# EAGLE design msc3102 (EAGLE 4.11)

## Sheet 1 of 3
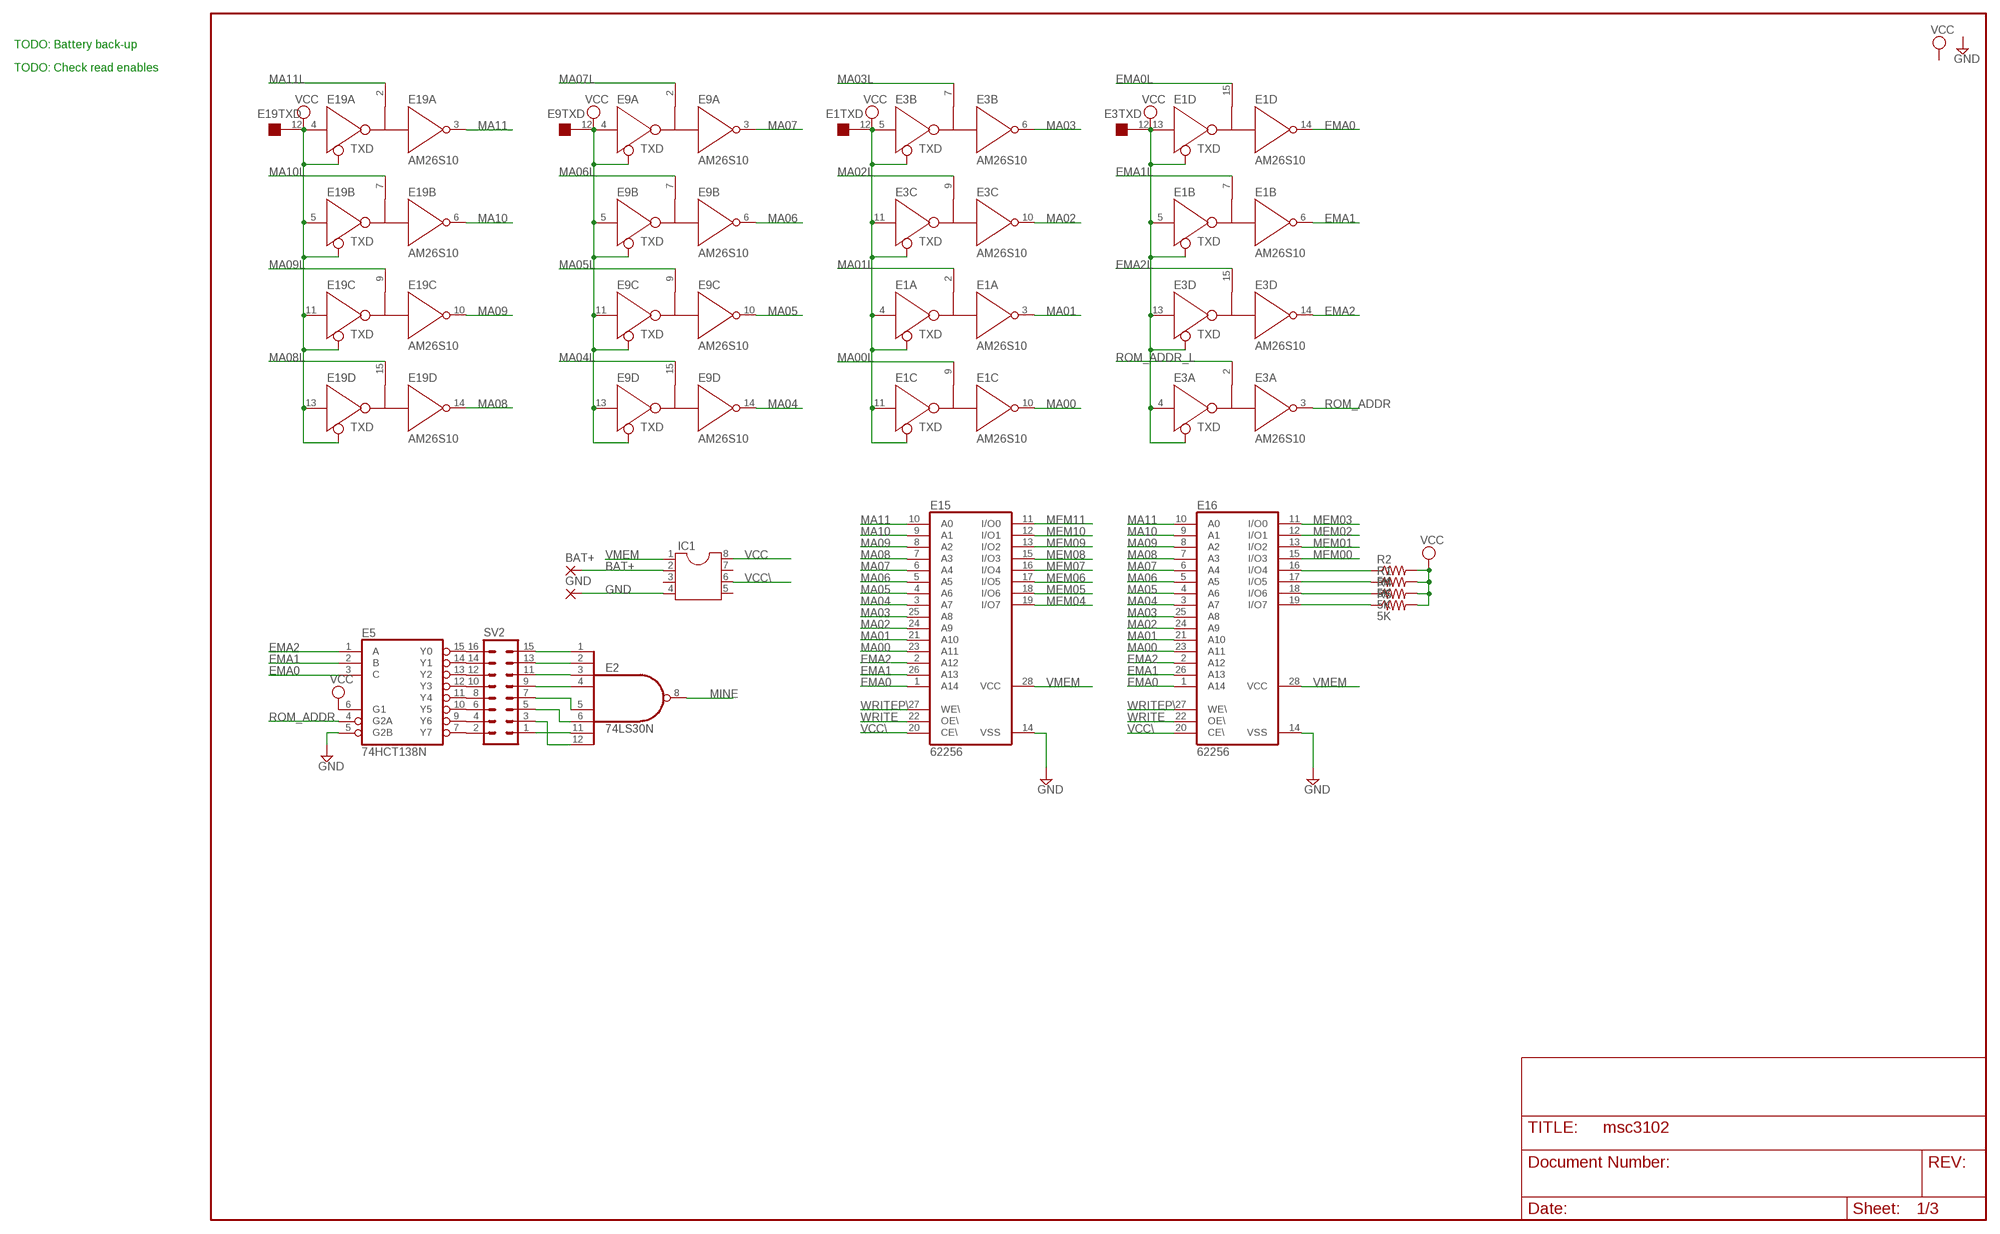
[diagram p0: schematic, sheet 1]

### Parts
BAT+  2,15/1,0  [2,15/1,0]
E1  AM26S10  [DIL16]
E2  74LS30N  [DIL14]
E3  AM26S10  [DIL16]
E5  74HCT138N  [DIL16]
E9  AM26S10  [DIL16]
E15  62256  58C256P  [DIL28-6]
E16  62256  58C256P  [DIL28-6]
E19  AM26S10  [DIL16]
GND  2,15/1,0  [2,15/1,0]
IC1  DIL8  [DIL08]
R1  5K  R-US_0207/10  [0207/10]
R2  5K  R-US_0207/10  [0207/10]
R4  5K  R-US_0207/10  [0207/10]
R5  5K  R-US_0207/10  [0207/10]
SV2  MA08-2  [MA08-2]

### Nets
BAT+: BAT+.1(P) IC1.2
EMA0: E1.14(D:R) E5.3(C) E15.1(A14) E16.1(A14)
EMA0L: E1.15(D:B) ; also sheet 3
EMA1: E1.6(B:R) E5.2(B) E15.26(A13) E16.26(A13)
EMA1L: E1.7(B:B) ; also sheet 3
EMA2: E3.14(D:R) E5.1(A) E15.2(A12) E16.2(A12)
EMA2L: E3.15(D:B) ; also sheet 3
GND [supply]: E5.5(G2B) E15.14(VSS) E16.14(VSS) GND.1(P) IC1.4 ; also sheet 2,3
MA00: E1.10(C:R) E15.23(A11) E16.23(A11)
MA00L: E1.9(C:B) ; also sheet 3
MA01: E1.3(A:R) E15.21(A10) E16.21(A10)
MA01L: E1.2(A:B) ; also sheet 3
MA02: E3.10(C:R) E15.24(A9) E16.24(A9)
MA02L: E3.9(C:B) ; also sheet 3
MA03: E3.6(B:R) E15.25(A8) E16.25(A8)
MA03L: E3.7(B:B) ; also sheet 3
MA04: E9.14(D:R) E15.3(A7) E16.3(A7)
MA04L: E9.15(D:B) ; also sheet 3
MA05: E9.10(C:R) E15.4(A6) E16.4(A6)
MA05L: E9.9(C:B) ; also sheet 3
MA06: E9.6(B:R) E15.5(A5) E16.5(A5)
MA06L: E9.7(B:B) ; also sheet 3
MA07: E9.3(A:R) E15.6(A4) E16.6(A4)
MA07L: E9.2(A:B) ; also sheet 3
MA08: E15.7(A3) E16.7(A3) E19.14(D:R)
MA08L: E19.15(D:B) ; also sheet 3
MA09: E15.8(A2) E16.8(A2) E19.10(C:R)
MA09L: E19.9(C:B) ; also sheet 3
MA10: E15.9(A1) E16.9(A1) E19.6(B:R)
MA10L: E19.7(B:B) ; also sheet 3
MA11: E15.10(A0) E16.10(A0) E19.3(A:R)
MA11L: E19.2(A:B) ; also sheet 3
MEM00: E16.15(I/O3) ; also sheet 2
MEM01: E16.13(I/O2) ; also sheet 2
MEM02: E16.12(I/O1) ; also sheet 2
MEM03: E16.11(I/O0) ; also sheet 2
MEM04: E15.19(I/O7) ; also sheet 2
MEM05: E15.18(I/O6) ; also sheet 2
MEM06: E15.17(I/O5) ; also sheet 2
MEM07: E15.16(I/O4) ; also sheet 2
MEM08: E15.15(I/O3) ; also sheet 2
MEM09: E15.13(I/O2) ; also sheet 2
MEM10: E15.12(I/O1) ; also sheet 2
MEM11: E15.11(I/O0) ; also sheet 2
MINE: E2.8(O) ; also sheet 2
N$1: E5.7(Y7) SV2.2
N$18: E5.9(Y6) SV2.4
N$19: E5.10(Y5) SV2.6
N$20: E5.11(Y4) SV2.8
N$21: E5.12(Y3) SV2.10
N$22: E5.13(Y2) SV2.12
N$23: E5.14(Y1) SV2.14
N$24: E5.15(Y0) SV2.16
N$26: E2.4(I3) SV2.9
N$27: E2.3(I2) SV2.11
N$28: E2.2(I1) SV2.13
N$29: E2.1(I0) SV2.15
N$30: E2.5(I4) SV2.7
N$31: E2.11(I6) SV2.1
N$32: E2.12(I7) SV2.3
N$33: E2.6(I5) SV2.5
N$35: E16.18(I/O6) R4.1
N$38: E16.16(I/O4) R2.1
N$44: E16.17(I/O5) R1.1
N$45: E16.19(I/O7) R5.1
ROM_ADDR: E3.3(A:R) E5.4(G2A)
ROM_ADDR_L: E3.2(A:B) ; also sheet 3
VCC [supply]: E1.4(A:D) E1.5(B:D) E1.11(C:D) E1.12(TXD:TXD) E1.13(D:D) E3.4(A:D) E3.5(B:D) E3.11(C:D) E3.12(TXD:TXD) E3.13(D:D) E5.6(G1) E9.4(A:D) E9.5(B:D) E9.11(C:D) E9.12(TXD:TXD) E9.13(D:D) E19.4(A:D) E19.5(B:D) E19.11(C:D) E19.12(TXD:TXD) E19.13(D:D) IC1.8 R1.2 R2.2 R4.2 R5.2 ; also sheet 2,3
VCC\: E15.20(CE\) E16.20(CE\) IC1.6
VMEM: E15.28(VCC) E16.28(VCC) IC1.1
WRITE: E15.22(OE\) E16.22(OE\) ; also sheet 2,3
WRITEP\: E15.27(WE\) E16.27(WE\) ; also sheet 2
Unconnected: IC1.3 IC1.5 IC1.7

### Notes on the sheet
- TODO: Battery back-up
- TODO: Check read enables

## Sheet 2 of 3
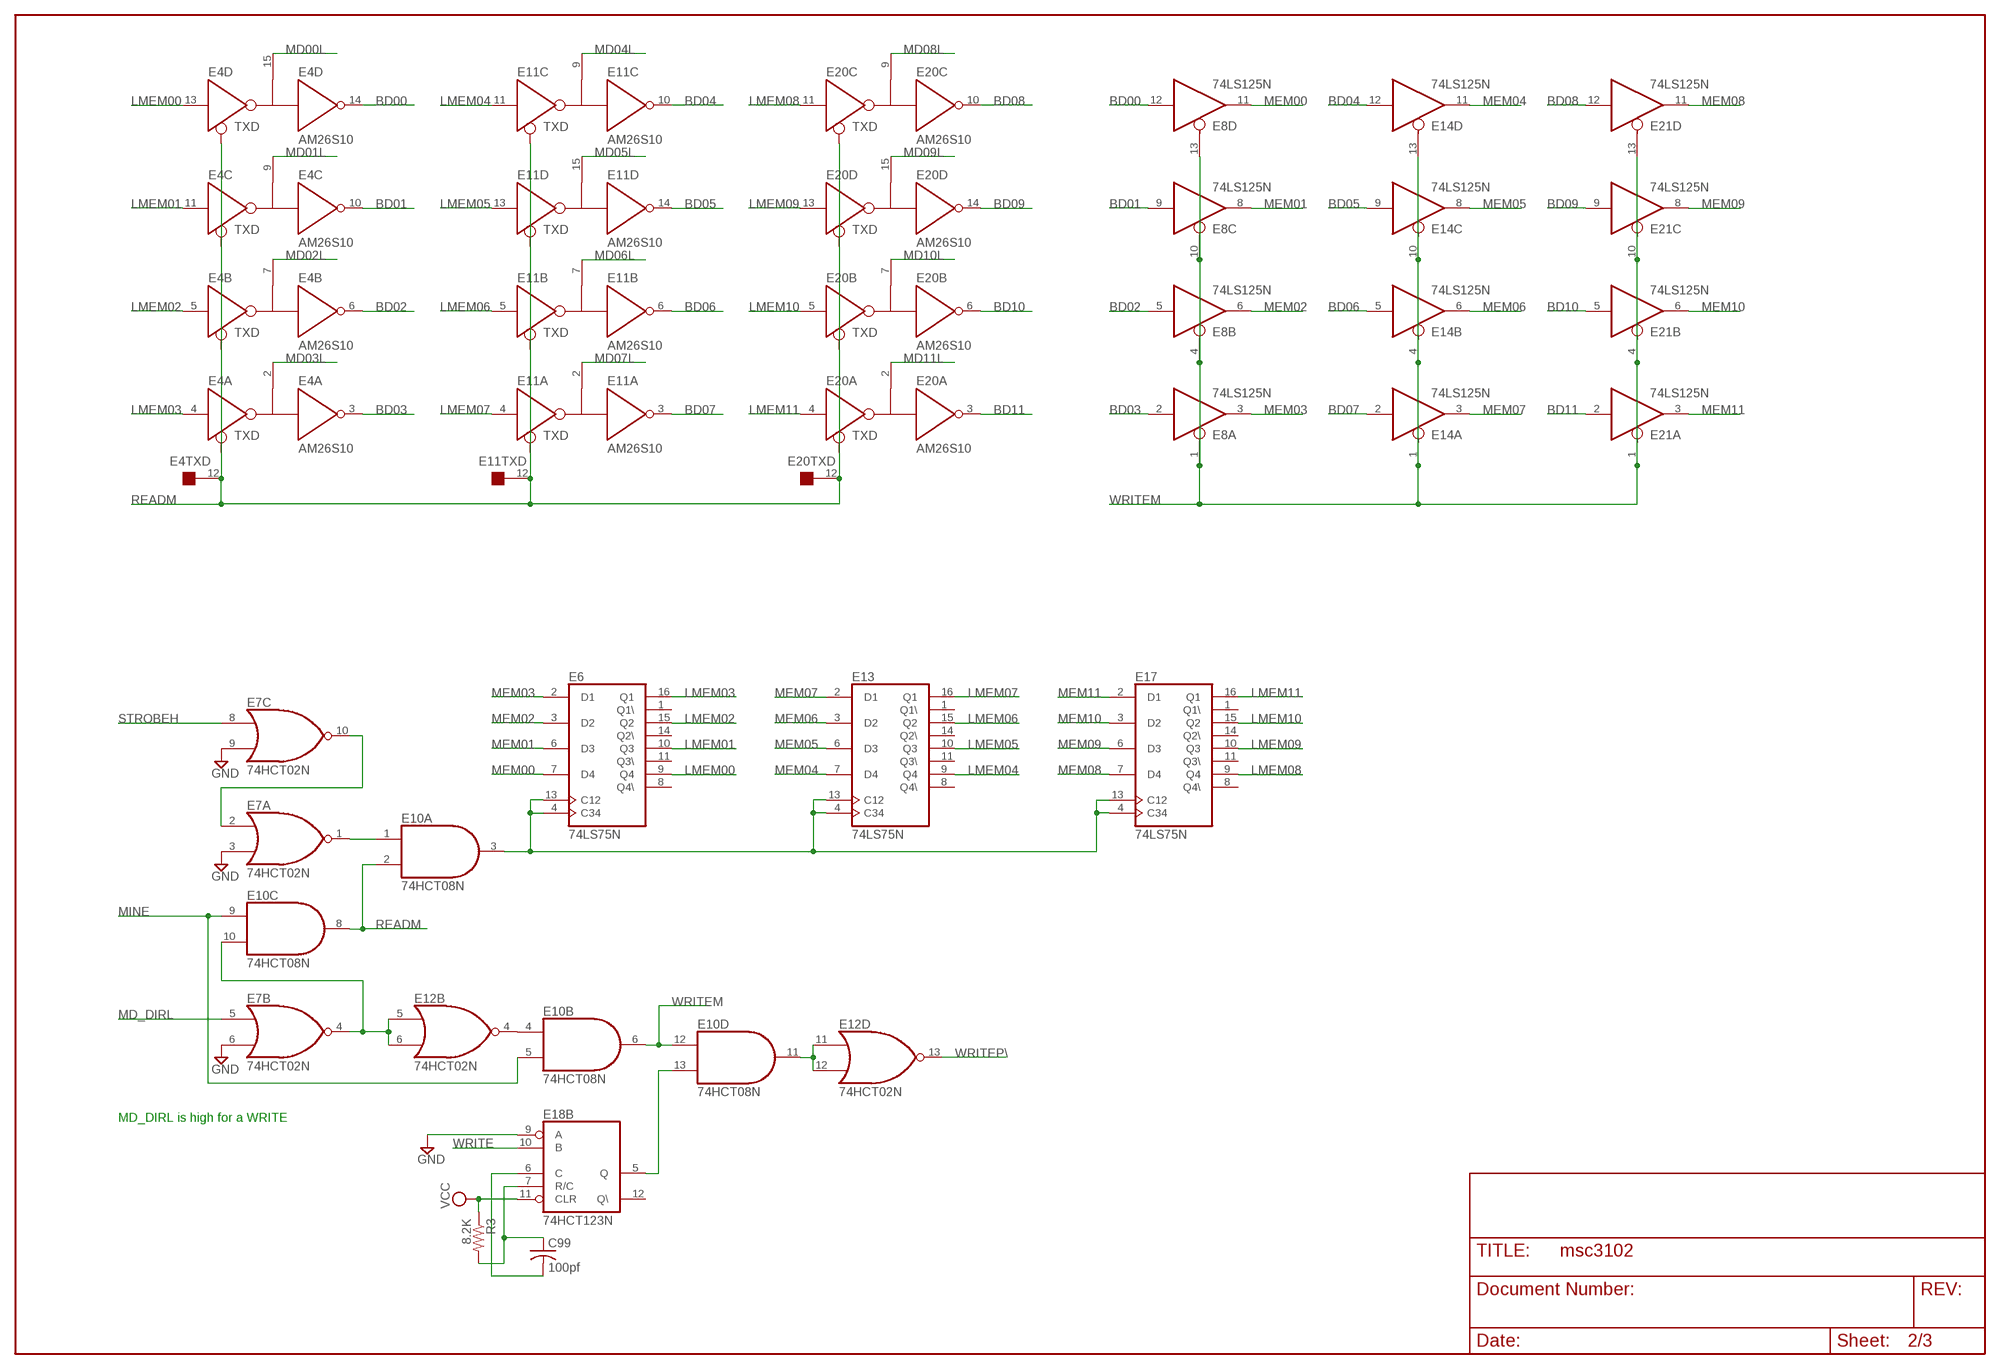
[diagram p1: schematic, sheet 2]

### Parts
C99  100pf  C-US050-025X075  [C050-025X075]
E4  AM26S10  [DIL16]
E6  74LS75N  [DIL16]
E7  74HCT02N  [DIL14]
E8  74LS125N  [DIL14]
E10  74HCT08N  74LS08N  [DIL14]
E11  AM26S10  [DIL16]
E12  74HCT02N  [DIL14]
E13  74LS75N  [DIL16]
E14  74LS125N  [DIL14]
E17  74LS75N  [DIL16]
E18  74HCT123N  [DIL16]
E20  AM26S10  [DIL16]
E21  74LS125N  [DIL14]
R3  8.2K  R-US_0207/10  [0207/10]

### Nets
BD00: E4.14(D:R) E8.12(D:I)
BD01: E4.10(C:R) E8.9(C:I)
BD02: E4.6(B:R) E8.5(B:I)
BD03: E4.3(A:R) E8.2(A:I)
BD04: E11.10(C:R) E14.12(D:I)
BD05: E11.14(D:R) E14.9(C:I)
BD06: E11.6(B:R) E14.5(B:I)
BD07: E11.3(A:R) E14.2(A:I)
BD08: E20.10(C:R) E21.12(D:I)
BD09: E20.14(D:R) E21.9(C:I)
BD10: E20.6(B:R) E21.5(B:I)
BD11: E20.3(A:R) E21.2(A:I)
GND [supply]: E7.3(A:I1) E7.6(B:I1) E7.9(C:I1) E18.9(B:A) ; also sheet 1,3
LMEM00: E4.13(D:D) E6.9(Q4)
LMEM01: E4.11(C:D) E6.10(Q3)
LMEM02: E4.5(B:D) E6.15(Q2)
LMEM03: E4.4(A:D) E6.16(Q1)
LMEM04: E11.11(C:D) E13.9(Q4)
LMEM05: E11.13(D:D) E13.10(Q3)
LMEM06: E11.5(B:D) E13.15(Q2)
LMEM07: E11.4(A:D) E13.16(Q1)
LMEM08: E17.9(Q4) E20.11(C:D)
LMEM09: E17.10(Q3) E20.13(D:D)
LMEM10: E17.15(Q2) E20.5(B:D)
LMEM11: E17.16(Q1) E20.4(A:D)
MD00L: E4.15(D:B) ; also sheet 3
MD01L: E4.9(C:B) ; also sheet 3
MD02L: E4.7(B:B) ; also sheet 3
MD03L: E4.2(A:B) ; also sheet 3
MD04L: E11.9(C:B) ; also sheet 3
MD05L: E11.15(D:B) ; also sheet 3
MD06L: E11.7(B:B) ; also sheet 3
MD07L: E11.2(A:B) ; also sheet 3
MD08L: E20.9(C:B) ; also sheet 3
MD09L: E20.15(D:B) ; also sheet 3
MD10L: E20.7(B:B) ; also sheet 3
MD11L: E20.2(A:B) ; also sheet 3
MD_DIRL: E7.5(B:I0) ; also sheet 3
MEM00: E6.7(D4) E8.11(D:O) ; also sheet 1
MEM01: E6.6(D3) E8.8(C:O) ; also sheet 1
MEM02: E6.3(D2) E8.6(B:O) ; also sheet 1
MEM03: E6.2(D1) E8.3(A:O) ; also sheet 1
MEM04: E13.7(D4) E14.11(D:O) ; also sheet 1
MEM05: E13.6(D3) E14.8(C:O) ; also sheet 1
MEM06: E13.3(D2) E14.6(B:O) ; also sheet 1
MEM07: E13.2(D1) E14.3(A:O) ; also sheet 1
MEM08: E17.7(D4) E21.11(D:O) ; also sheet 1
MEM09: E17.6(D3) E21.8(C:O) ; also sheet 1
MEM10: E17.3(D2) E21.6(B:O) ; also sheet 1
MEM11: E17.2(D1) E21.3(A:O) ; also sheet 1
MINE: E10.5(B:I1) E10.9(C:I0) ; also sheet 1
N$25: C99.1 E18.7(B:R/C) R3.2
N$34: C99.2 E18.6(B:C)
N$36: E10.4(B:I0) E12.4(B:O)
N$37: E7.4(B:O) E10.10(C:I1) E12.5(B:I0) E12.6(B:I1)
N$39: E7.1(A:O) E10.1(A:I0)
N$40: E7.2(A:I0) E7.10(C:O)
N$41: E6.4(C34) E6.13(C12) E10.3(A:O) E13.4(C34) E13.13(C12) E17.4(C34) E17.13(C12)
N$42: E10.13(D:I1) E18.5(B:Q)
N$43: E10.11(D:O) E12.11(D:I0) E12.12(D:I1)
READM: E4.12(TXD:TXD) E10.2(A:I1) E10.8(C:O) E11.12(TXD:TXD) E20.12(TXD:TXD)
STROBEH: E7.8(C:I0) ; also sheet 3
VCC [supply]: E18.11(B:CLR) R3.1 ; also sheet 1,3
WRITE: E18.10(B:B) ; also sheet 1,3
WRITEM: E8.1(A:OE) E8.4(B:OE) E8.10(C:OE) E8.13(D:OE) E10.6(B:O) E10.12(D:I0) E14.1(A:OE) E14.4(B:OE) E14.10(C:OE) E14.13(D:OE) E21.1(A:OE) E21.4(B:OE) E21.10(C:OE) E21.13(D:OE)
WRITEP\: E12.13(D:O) ; also sheet 1
Unconnected: E6.1(Q1\) E6.8(Q4\) E6.11(Q3\) E6.14(Q2\) E7.11(D:I0) E7.12(D:I1) E7.13(D:O) E12.1(A:O) E12.2(A:I0) E12.3(A:I1) E12.8(C:I0) E12.9(C:I1) E12.10(C:O) E13.1(Q1\) E13.8(Q4\) E13.11(Q3\) E13.14(Q2\) E17.1(Q1\) E17.8(Q4\) E17.11(Q3\) E17.14(Q2\) E18.1(A:A) E18.2(A:B) E18.3(A:CLR) E18.4(A:Q\) E18.12(B:Q\) E18.13(A:Q) E18.14(A:C) E18.15(A:R/C)

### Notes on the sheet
- MD_DIRL is high for a WRITE

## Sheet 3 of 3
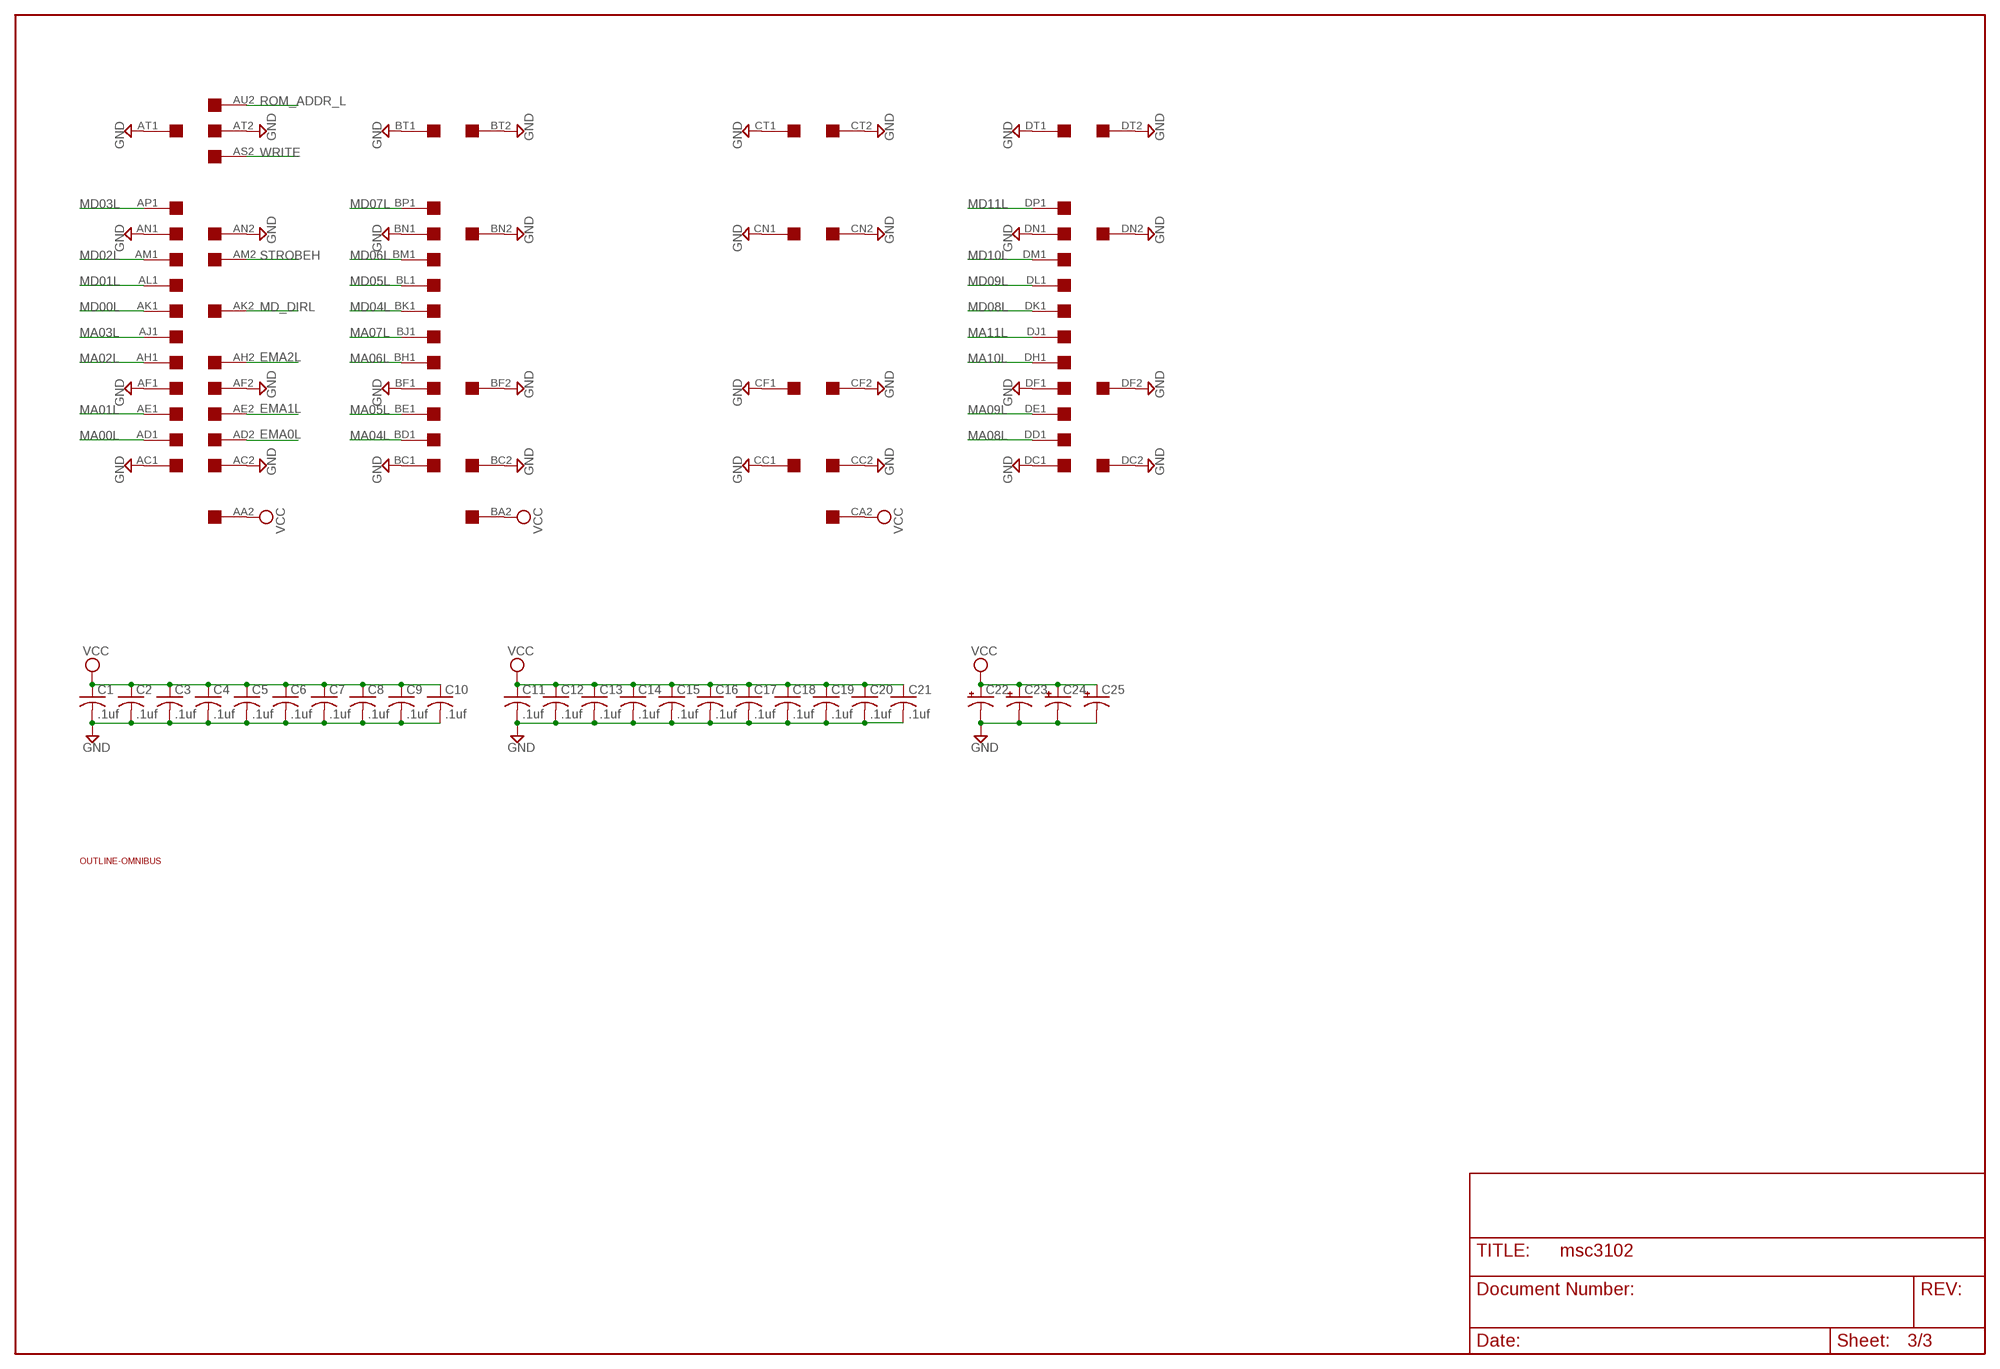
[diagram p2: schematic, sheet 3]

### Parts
C1  .1uf  C-US050-025X075  [C050-025X075]
C2  .1uf  C-US050-025X075  [C050-025X075]
C3  .1uf  C-US050-025X075  [C050-025X075]
C4  .1uf  C-US050-025X075  [C050-025X075]
C5  .1uf  C-US050-025X075  [C050-025X075]
C6  .1uf  C-US050-025X075  [C050-025X075]
C7  .1uf  C-US050-025X075  [C050-025X075]
C8  .1uf  C-US050-025X075  [C050-025X075]
C9  .1uf  C-US050-025X075  [C050-025X075]
C10  .1uf  C-US050-025X075  [C050-025X075]
C11  .1uf  C-US050-025X075  [C050-025X075]
C12  .1uf  C-US050-025X075  [C050-025X075]
C13  .1uf  C-US050-025X075  [C050-025X075]
C14  .1uf  C-US050-025X075  [C050-025X075]
C15  .1uf  C-US050-025X075  [C050-025X075]
C16  .1uf  C-US050-025X075  [C050-025X075]
C17  .1uf  C-US050-025X075  [C050-025X075]
C18  .1uf  C-US050-025X075  [C050-025X075]
C19  .1uf  C-US050-025X075  [C050-025X075]
C20  .1uf  C-US050-025X075  [C050-025X075]
C21  .1uf  C-US050-025X075  [C050-025X075]
C22  CPOL-USE22-6AXIAL  [E22-6]
C23  CPOL-USE22-6AXIAL  [E22-6]
C24  CPOL-USE22-6AXIAL  [E22-6]
C25  CPOL-USE22-6AXIAL  [E22-6]
U$1  OUTLINE-OMNIBUS  [OMNIBUS]
U$2  QUAD  [EDGE-CON8]

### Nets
EMA0L: U$2.AD2 ; also sheet 1
EMA1L: U$2.AE2 ; also sheet 1
EMA2L: U$2.AH2 ; also sheet 1
GND [supply]: C1.2 C2.2 C3.2 C4.2 C5.2 C6.2 C7.2 C8.2 C9.2 C10.2 C11.2 C12.2 C13.2 C14.2 C15.2 C16.2 C17.2 C18.2 C19.2 C20.2 C21.2 C22.- C23.- C24.- C25.- U$2.AC1 U$2.AC2 U$2.AF1 U$2.AF2 U$2.AN1 U$2.AN2 U$2.AT1 U$2.AT2 U$2.BC1 U$2.BC2 U$2.BF1 U$2.BF2 U$2.BN1 U$2.BN2 U$2.BT1 U$2.BT2 U$2.CC1 U$2.CC2 U$2.CF1 U$2.CF2 U$2.CN1 U$2.CN2 U$2.CT1 U$2.CT2 U$2.DC1 U$2.DC2 U$2.DF1 U$2.DF2 U$2.DN1 U$2.DN2 U$2.DT1 U$2.DT2 ; also sheet 1,2
MA00L: U$2.AD1 ; also sheet 1
MA01L: U$2.AE1 ; also sheet 1
MA02L: U$2.AH1 ; also sheet 1
MA03L: U$2.AJ1 ; also sheet 1
MA04L: U$2.BD1 ; also sheet 1
MA05L: U$2.BE1 ; also sheet 1
MA06L: U$2.BH1 ; also sheet 1
MA07L: U$2.BJ1 ; also sheet 1
MA08L: U$2.DD1 ; also sheet 1
MA09L: U$2.DE1 ; also sheet 1
MA10L: U$2.DH1 ; also sheet 1
MA11L: U$2.DJ1 ; also sheet 1
MD00L: U$2.AK1 ; also sheet 2
MD01L: U$2.AL1 ; also sheet 2
MD02L: U$2.AM1 ; also sheet 2
MD03L: U$2.AP1 ; also sheet 2
MD04L: U$2.BK1 ; also sheet 2
MD05L: U$2.BL1 ; also sheet 2
MD06L: U$2.BM1 ; also sheet 2
MD07L: U$2.BP1 ; also sheet 2
MD08L: U$2.DK1 ; also sheet 2
MD09L: U$2.DL1 ; also sheet 2
MD10L: U$2.DM1 ; also sheet 2
MD11L: U$2.DP1 ; also sheet 2
MD_DIRL: U$2.AK2 ; also sheet 2
ROM_ADDR_L: U$2.AU2 ; also sheet 1
STROBEH: U$2.AM2 ; also sheet 2
VCC [supply]: C1.1 C2.1 C3.1 C4.1 C5.1 C6.1 C7.1 C8.1 C9.1 C10.1 C11.1 C12.1 C13.1 C14.1 C15.1 C16.1 C17.1 C18.1 C19.1 C20.1 C21.1 C22.+ C23.+ C24.+ C25.+ U$2.AA2 U$2.BA2 U$2.CA2 ; also sheet 1,2
WRITE: U$2.AS2 ; also sheet 1,2
Unconnected: U$2.AA1 U$2.AB1 U$2.AB2 U$2.AJ2 U$2.AL2 U$2.AP2 U$2.AR1 U$2.AR2 U$2.AS1 U$2.AU1 U$2.AV1 U$2.AV2 U$2.BA1 U$2.BB1 U$2.BB2 U$2.BD2 U$2.BE2 U$2.BH2 U$2.BJ2 U$2.BK2 U$2.BL2 U$2.BM2 U$2.BP2 U$2.BR1 U$2.BR2 U$2.BS1 U$2.BS2 U$2.BU1 U$2.BU2 U$2.BV1 U$2.BV2 U$2.CA1 U$2.CB1 U$2.CB2 U$2.CD1 U$2.CD2 U$2.CE1 U$2.CE2 U$2.CH1 U$2.CH2 U$2.CJ1 U$2.CJ2 U$2.CK1 U$2.CK2 U$2.CL1 U$2.CL2 U$2.CM1 U$2.CM2 U$2.CP1 U$2.CP2 U$2.CR1 U$2.CR2 U$2.CS1 U$2.CS2 U$2.CU1 U$2.CU2 U$2.CV1 U$2.CV2 U$2.DA1 U$2.DA2 U$2.DB1 U$2.DB2 U$2.DD2 U$2.DE2 U$2.DH2 U$2.DJ2 U$2.DK2 U$2.DL2 U$2.DM2 U$2.DP2 U$2.DR1 U$2.DR2 U$2.DS1 U$2.DS2 U$2.DU1 U$2.DU2 U$2.DV1 U$2.DV2

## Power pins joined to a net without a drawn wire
GND: E1.1(GND:GND) E1.8(PWR:GND) E2.7(GND) E3.1(GND:GND) E3.8(PWR:GND) E4.1(GND:GND) E4.8(PWR:GND) E5.8(GND) E6.12(GND) E7.7(P:GND) E8.7(P:GND) E9.1(GND:GND) E9.8(PWR:GND) E10.7(P:GND) E11.1(GND:GND) E11.8(PWR:GND) E12.7(P:GND) E13.12(GND) E14.7(P:GND) E17.12(GND) E18.8(P:GND) E19.1(GND:GND) E19.8(PWR:GND) E20.1(GND:GND) E20.8(PWR:GND) E21.7(P:GND)
VCC: E1.16(PWR:VCC) E2.14(VCC) E3.16(PWR:VCC) E4.16(PWR:VCC) E5.16(VCC) E6.5(VCC) E7.14(P:VCC) E8.14(P:VCC) E9.16(PWR:VCC) E10.14(P:VCC) E11.16(PWR:VCC) E12.14(P:VCC) E13.5(VCC) E14.14(P:VCC) E17.5(VCC) E18.16(P:VCC) E19.16(PWR:VCC) E20.16(PWR:VCC) E21.14(P:VCC)

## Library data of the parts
BAT+ GND = wirepad:2,15/1,0: THROUGH-HOLE PAD
C1-C21 C99 = rcl:C-US: CAPACITOR, American symbol
C22-C25 = rcl:CPOL-US: POLARIZED CAPACITOR, American symbol
E1 E3 E4 E9 E11 E19 E20 = dec-con:AM26S10: Bus Transceiver
E2 = 74xx-jameco:74*30: 8-input NAND gate
E5 = 74xx-jameco:74*138: 3-line to 8-line DECODER/DEMULTIPLEXER
E6 E13 E17 = 74xx-jameco:74*75: 4-bit bistable LATCH
E7 E12 = 74xx-jameco:74*02: Quad 2-input NOR gate
E8 E14 E21 = 74xx-jameco:74*125: Quad bus BUFFER, 3-state
E10 = 74xx-jameco:74*08: Quad 2-input AND gate
E15 E16 = memory-hitachi:58C256P: MEMORY
E18 = 74xx-jameco:74*123: Retriggerable monostable MULTIVIBRATOR
IC1 = ic-package:DIL8: Dual In Line
R1-R5 = rcl:R-US_: RESISTOR, American symbol
SV2 = con-lstb:MA08-2: PIN HEADER
U$1 = dec-con:OUTLINE-*: Board outlines for DEC boards.
U$2 = dec-con:QUAD: Quad-Height DEC board

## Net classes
1 supply: width 0.762 mm

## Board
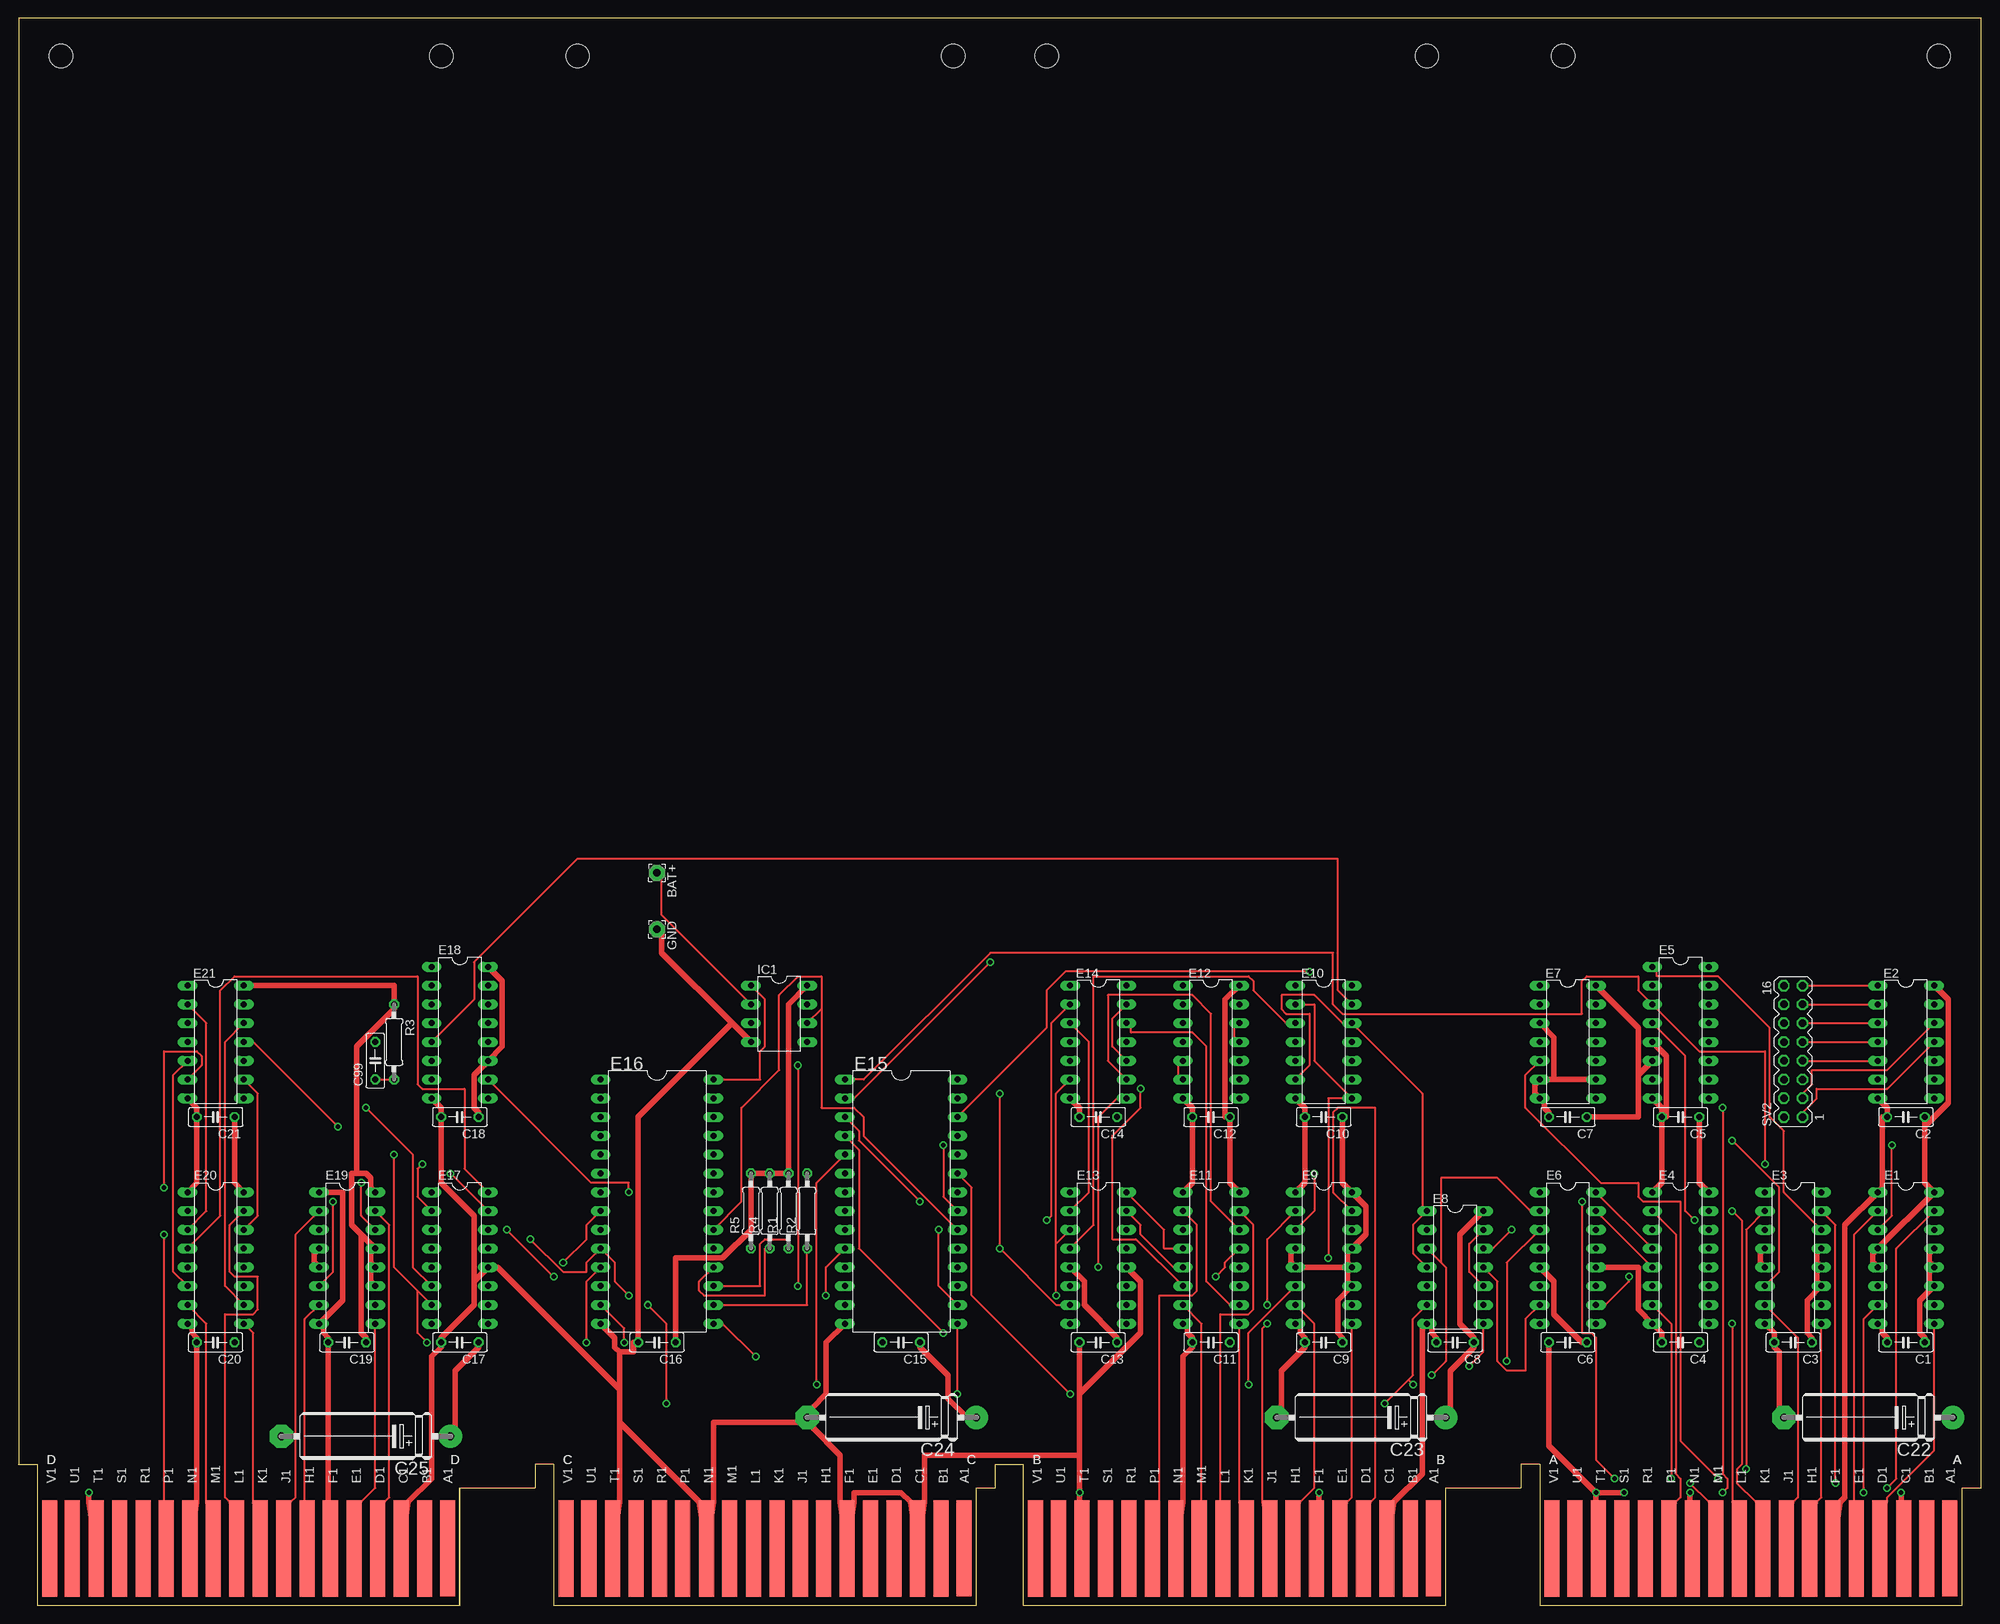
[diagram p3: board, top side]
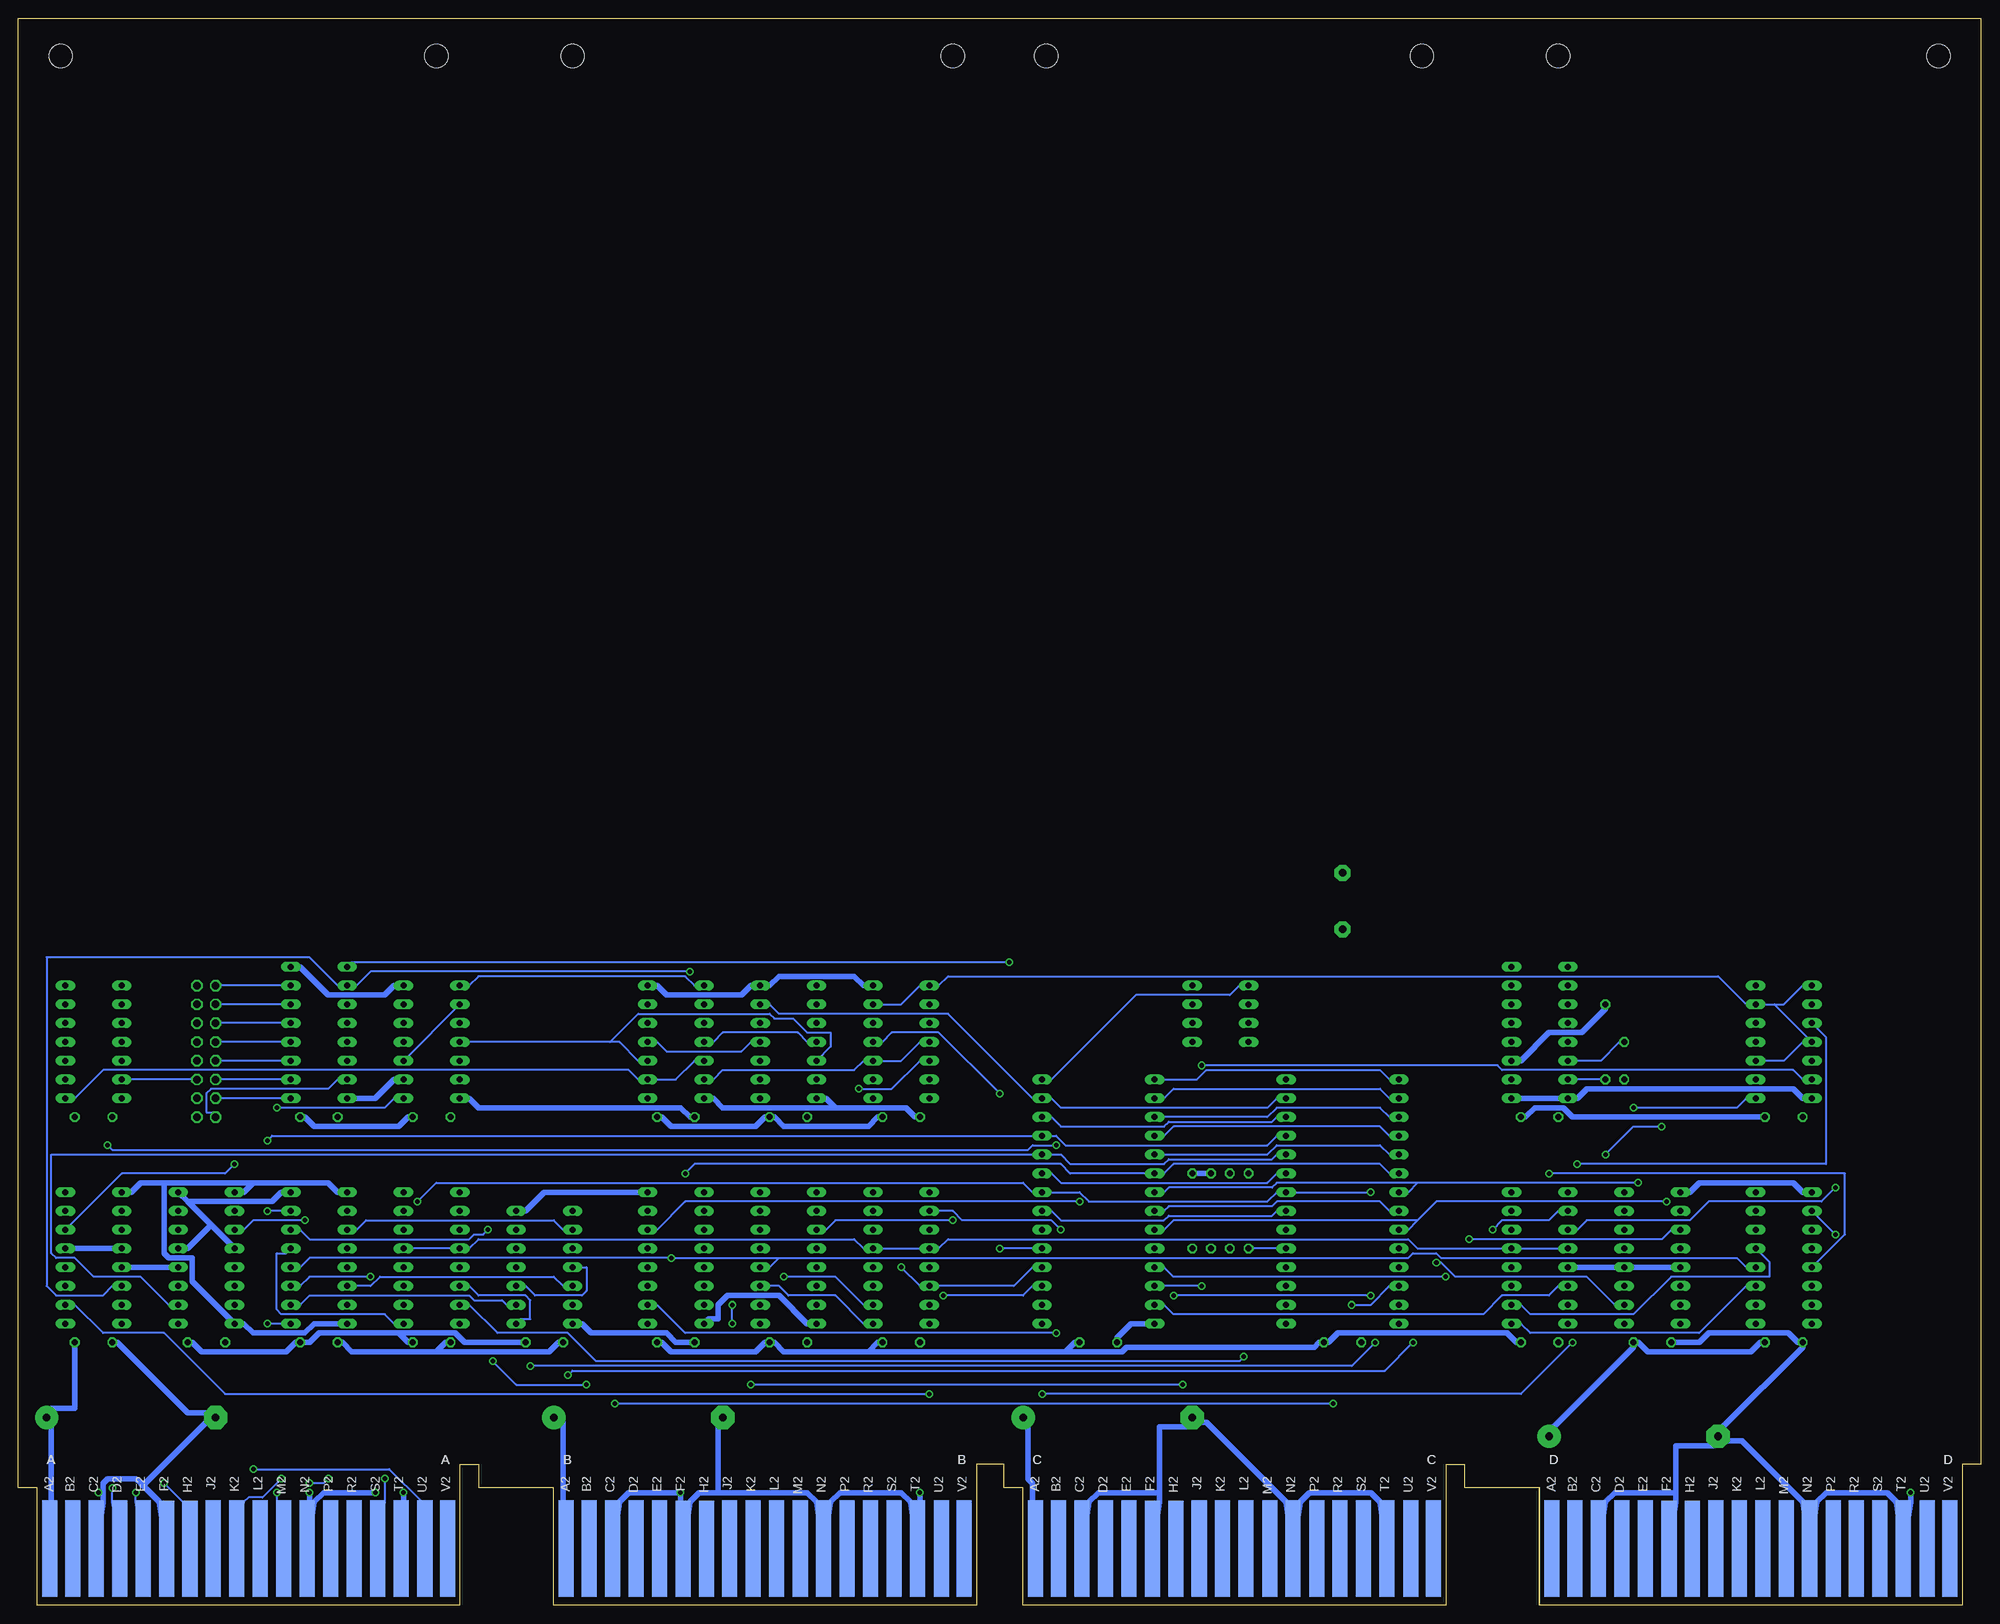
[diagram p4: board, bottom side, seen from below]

Size 265.43 x 214.63 mm. Coordinates in mm from the lower left corner, seen from the top.
Copper layers (1*16): Top 0.035mm / dielectric 1.5mm / Bottom 0.035mm
Design rules "default": minimum track width 10mil, minimum drill 24mil, track to track 8mil, track to pad 8mil, pad to pad 8mil, via to via 8mil, smd to smd 8mil, copper to edge 25mil, drill to drill 8mil, minimum pad ring 10mil, minimum via ring 8mil, stop-mask expansion 4mil, vias tented up to drill 0mil, thermal gap 10mil

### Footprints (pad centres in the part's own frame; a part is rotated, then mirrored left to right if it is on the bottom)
2,15/1,0 = drill 1.016 pad 2.159 octagon: 1 0,0
C050-025X075 = drill 0.813 octagon: 1 -2.54,0; 2 2.54,0
E22-6 = drill 1.016 pad 3.15 round: + -11.43,0 | drill 1.016 pad 3.15 octagon: - 11.43,0
DIL16 = drill 0.813 long: 1 -8.89,-3.81; 2 -6.35,-3.81; 3 -3.81,-3.81; 4 -1.27,-3.81; 5 1.27,-3.81; 6 3.81,-3.81; 7 6.35,-3.81; 8 8.89,-3.81; 9 8.89,3.81; 10 6.35,3.81; 11 3.81,3.81; 12 1.27,3.81; 13 -1.27,3.81; 14 -3.81,3.81; 15 -6.35,3.81; 16 -8.89,3.81
DIL14 = drill 0.813 long: 1 -7.62,-3.81; 2 -5.08,-3.81; 3 -2.54,-3.81; 4 0,-3.81; 5 2.54,-3.81; 6 5.08,-3.81; 7 7.62,-3.81; 8 7.62,3.81; 9 5.08,3.81; 10 2.54,3.81; 11 0,3.81; 12 -2.54,3.81; 13 -5.08,3.81; 14 -7.62,3.81
DIL28-6 = drill 0.813 long: 1 -16.51,-7.62; 2 -13.97,-7.62; 3 -11.43,-7.62; 4 -8.89,-7.62; 5 -6.35,-7.62; 6 -3.81,-7.62; 7 -1.27,-7.62; 8 1.27,-7.62; 9 3.81,-7.62; 10 6.35,-7.62; 11 8.89,-7.62; 12 11.43,-7.62; 13 13.97,-7.62; 14 16.51,-7.62; 15 16.51,7.62; 16 13.97,7.62; 17 11.43,7.62; 18 8.89,7.62; 19 6.35,7.62; 20 3.81,7.62; 21 1.27,7.62; 22 -1.27,7.62; 23 -3.81,7.62; 24 -6.35,7.62; 25 -8.89,7.62; 26 -11.43,7.62; 27 -13.97,7.62; 28 -16.51,7.62
DIL08 = drill 0.813 long: 1 -3.81,-3.81; 2 -1.27,-3.81; 3 1.27,-3.81; 4 3.81,-3.81; 5 3.81,3.81; 6 1.27,3.81; 7 -1.27,3.81; 8 -3.81,3.81
0207/10 = drill 0.813 octagon: 1 -5.08,0; 2 5.08,0
MA08-2 = drill 1.016 octagon: 1 -8.89,-1.27; 2 -8.89,1.27; 3 -6.35,-1.27; 4 -6.35,1.27; 5 -3.81,-1.27; 6 -3.81,1.27; 7 -1.27,-1.27; 8 -1.27,1.27; 9 1.27,-1.27; 10 1.27,1.27; 11 3.81,-1.27; 12 3.81,1.27; 13 6.35,-1.27; 14 6.35,1.27; 15 8.89,-1.27; 16 8.89,1.27
OMNIBUS = hole 3.175: 208.915,209.55; 259.715,209.55; 190.5,209.55; 139.065,209.55; 75.616,209.55; 126.416,209.55; 57.201,209.55; 5.766,209.55
EDGE-CON8 = smd 2.032 x 13.017: AA1 261.223,7.709; AB1 258.118,7.684; AC1 254.956,7.684; AD1 251.765,7.684; AE1 248.59,7.693; AF1 245.389,7.668; AH1 242.24,7.668; AJ1 239.09,7.668; AK1 235.915,7.668; AL1 232.74,7.693; AM1 229.54,7.693; AN1 226.39,7.693; AP1 223.19,7.668; AR1 220.04,7.668; AS1 216.865,7.693; AT1 213.69,7.693; AU1 210.49,7.693; AV1 207.404,7.668; BA1 191.373,7.709; BB1 188.268,7.684; BC1 185.106,7.684; BD1 181.915,7.684; BE1 178.74,7.693; BF1 175.539,7.668; BH1 172.39,7.668; BJ1 169.24,7.668; BK1 166.065,7.668; BL1 162.89,7.693; BM1 159.69,7.693; BN1 156.54,7.693; BP1 153.34,7.668; BR1 150.19,7.668; BS1 147.015,7.693; BT1 143.84,7.693; BU1 140.64,7.693; BV1 137.554,7.668; CA1 127.873,7.709; CB1 124.768,7.684; CC1 121.606,7.684; CD1 118.415,7.684; CE1 115.24,7.693; CF1 112.039,7.668; CH1 108.89,7.668; CJ1 105.74,7.668; CK1 102.565,7.668; CL1 99.39,7.693; CM1 96.19,7.693; CN1 93.04,7.693; CP1 89.84,7.668; CR1 86.69,7.668; CS1 83.515,7.693; CT1 80.34,7.693; CU1 77.14,7.693; CV1 74.054,7.668; DA1 58.023,7.709; DB1 54.918,7.684; DC1 51.756,7.684; DD1 48.565,7.684; DE1 45.39,7.693; DF1 42.189,7.668; DH1 39.04,7.668; DJ1 35.89,7.668; DK1 32.715,7.668; DL1 29.54,7.693; DM1 26.34,7.693; DN1 23.19,7.693; DP1 19.99,7.668; DR1 16.84,7.668; DS1 13.665,7.693; DT1 10.49,7.693; DU1 7.29,7.693; DV1 4.204,7.668 | smd 2.032 x 13.017 bottom: AA2 261.223,7.69; AB2 258.102,7.668; AC2 254.94,7.668; AD2 251.765,7.693; AE2 248.59,7.693; AF2 245.389,7.642; AH2 242.24,7.642; AJ2 239.09,7.668; AK2 235.915,7.668; AL2 232.74,7.693; AM2 229.54,7.693; AN2 226.39,7.693; AP2 223.19,7.668; AR2 220.04,7.668; AS2 216.865,7.693; AT2 213.69,7.693; AU2 210.464,7.693; AV2 207.404,7.668; BA2 191.373,7.69; BB2 188.252,7.668; BC2 185.09,7.668; BD2 181.915,7.693; BE2 178.74,7.693; BF2 175.539,7.642; BH2 172.39,7.642; BJ2 169.24,7.668; BK2 166.065,7.668; BL2 162.89,7.693; BM2 159.69,7.693; BN2 156.54,7.693; BP2 153.34,7.668; BR2 150.19,7.668; BS2 147.015,7.693; BT2 143.84,7.693; BU2 140.614,7.693; BV2 137.554,7.668; CA2 127.873,7.69; CB2 124.752,7.668; CC2 121.59,7.668; CD2 118.415,7.693; CE2 115.24,7.693; CF2 112.039,7.642; CH2 108.89,7.642; CJ2 105.74,7.668; CK2 102.565,7.668; CL2 99.39,7.693; CM2 96.19,7.693; CN2 93.04,7.693; CP2 89.84,7.668; CR2 86.69,7.668; CS2 83.515,7.693; CT2 80.34,7.693; CU2 77.114,7.693; CV2 74.054,7.668; DA2 58.023,7.69; DB2 54.902,7.668; DC2 51.74,7.668; DD2 48.565,7.693; DE2 45.39,7.693; DF2 42.189,7.642; DH2 39.04,7.642; DJ2 35.89,7.668; DK2 32.715,7.668; DL2 29.54,7.693; DM2 26.34,7.693; DN2 23.19,7.693; DP2 19.99,7.668; DR2 16.84,7.668; DS2 13.665,7.693; DT2 10.49,7.693; DU2 7.264,7.693; DV2 4.204,7.668

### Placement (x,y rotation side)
BAT+  86.36,99.06 270 top
C1  255.27,35.56 180 top
C2  255.27,66.04 180 top
C3  240.03,35.56 180 top
C4  224.79,35.56 180 top
C5  224.79,66.04 180 top
C6  209.55,35.56 180 top
C7  209.55,66.04 180 top
C8  194.31,35.56 180 top
C9  176.53,35.56 180 top
C10  176.53,66.04 180 top
C11  161.29,35.56 180 top
C12  161.29,66.04 180 top
C13  146.05,35.56 180 top
C14  146.05,66.04 180 top
C15  119.38,35.56 180 top
C16  86.36,35.56 180 top
C17  59.69,35.56 180 top
C18  59.69,66.04 180 top
C19  44.45,35.56 180 top
C20  26.67,35.56 180 top
C21  26.67,66.04 180 top
C22  250.19,25.4 180 top
C23  181.61,25.4 180 top
C24  118.11,25.4 180 top
C25  46.99,22.86 180 top
C99  48.26,73.66 90 top
E1  255.27,46.99 270 top
E2  255.27,76.2 270 top
E3  240.03,46.99 270 top
E4  224.79,46.99 270 top
E5  224.79,77.47 270 top
E6  209.55,46.99 270 top
E7  209.55,76.2 270 top
E8  194.31,45.72 270 top
E9  176.53,46.99 270 top
E10  176.53,76.2 270 top
E11  161.29,46.99 270 top
E12  161.29,76.2 270 top
E13  146.05,46.99 270 top
E14  146.05,76.2 270 top
E15  119.38,54.61 270 top
E16  86.36,54.61 270 top
E17  59.69,46.99 270 top
E18  59.69,77.47 270 top
E19  44.45,46.99 270 top
E20  26.67,46.99 270 top
E21  26.67,76.2 270 top
GND  86.36,91.44 270 top
IC1  102.87,80.01 270 top
R1  104.14,53.34 90 top
R2  106.68,53.34 90 top
R3  50.8,76.2 270 top
R4  101.6,53.34 90 top
R5  99.06,53.34 90 top
SV2  240.03,74.93 90 top
U$1  0,0 0 top
U$2  0,0 0 top

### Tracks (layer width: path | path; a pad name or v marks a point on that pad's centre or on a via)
BAT+
  Top 0.254: IC1.2 87,93.35 87,98.43 BAT+.1
BD00  (via drill 0.61)
  Top 0.254: v201.93,50.8 199.39,48.26 E8.12
  Bottom 0.254: v201.93,50.8 202.56,50.17 203.84,50.17 204.47,49.53 226.06,49.53 227.33,50.8 E4.14
BD01
  Bottom 0.254: E8.9 199.39,40.64 200.03,41.28 203.84,41.28 204.47,41.91 226.06,41.91 227.33,40.64 E4.10
BD02
  Bottom 0.254: E8.5 191.77,43.18 193.04,44.45 216.53,44.45 217.81,43.18 E4.6
BD03
  Bottom 0.254: E8.2 191.77,50.8 193.04,52.07 218.44,52.07 219.71,50.8 E4.3
BD04
  Top 0.254: E11.10 163.83,40.64 160.66,43.82 160.66,75.57 158.75,77.47 150.5,77.47 150.5,78.11 E14.12
BD05
  Top 0.254: E11.14 161.29,54.61 161.29,80.01 158.75,82.55 147.32,82.55 147.32,73.66 E14.9
BD06  (via drill 0.61)
  Top 0.254: v151.76,69.85 151.76,67.31 147.96,63.5 147.96,49.53 151.13,49.53 E11.6
  Bottom 0.254: v151.76,69.85 147.32,69.85 143.51,73.66 E14.5
BD07  (via drill 0.61)
  Top 0.254: v139.06,52.07 139.7,52.71 139.7,78.74 E14.2
  Bottom 0.254: v139.06,52.07 154.94,52.07 156.21,50.8 E11.3
BD08
  Top 0.254: E20.10 27.94,43.18 27.94,76.2 E21.12
BD09
  Top 0.254: E20.14 32.38,52.71 32.38,69.22 E21.9
BD10
  Top 0.254: E20.6 20.95,45.09 20.95,71.76 E21.5
BD11
  Top 0.254: E20.3 25.4,53.34 25.4,78.74 E21.2
EMA0  (via drill 0.61)
  Top 0.254: v236.22,59.69 236.22,74.93 227.33,74.93 E5.3 219.07,83.19 219.07,85.09 212.09,85.09 211.46,84.46 211.46,80.01 179.07,80.01 177.8,81.28 177.8,88.27 131.44,88.27 114.3,71.12 E15.1
  Bottom 0.254: E16.1 80.01,71.12 81.28,72.39 104.78,72.39 106.05,71.12 E15.1 | v236.22,59.69 237.49,58.42 251.46,58.42 E1.14
EMA0L  (via drill 0.61)
  Top 0.254: v252.73,15.88 254,17.15 254,48.26 E1.15
  Bottom 0.254: v252.73,15.88 252.73,13.97 U$2.AD2
EMA1  (via drill 0.61)
  Top 0.254: v174.62,85.73 141.6,85.73 139.06,83.19 139.06,78.11 E15.26
  Bottom 0.254: E16.26 95.25,66.04 95.89,65.41 109.86,65.41 110.49,64.77 124.46,64.77 125.73,66.04 E15.26 | E1.6 252.73,43.18 254,41.91 260.35,41.91 261.62,43.18 261.62,87.63 226.06,87.63 222.25,83.82 E5.2 219.71,83.82 217.81,85.73 v174.62,85.73
EMA1L  (via drill 0.61)
  Top 0.254: v249.56,15.24 249.56,38.74 E1.7
  Bottom 0.254: v249.56,15.24 249.56,13.97 U$2.AE2
EMA2  (via drill 0.61)
  Top 0.254: E3.14 238.76,55.88 238.76,64.14 236.85,66.04 236.85,78.11 229.87,85.09 221.62,85.09 221.62,85.73 E5.1 | v131.44,87 113.03,68.58 E15.2
  Bottom 0.254: E16.2 80.01,68.58 81.28,69.85 109.22,69.85 110.49,68.58 E15.2 | v131.44,87 220.34,87 E5.1
EMA2L  (via drill 0.61)
  Top 0.254: v245.75,16.51 245.75,51.44 E3.15
  Bottom 0.254: v245.75,16.51 243.21,13.97 U$2.AH2
GND  (via drill 0.61)
  Top 0.762: E11.8 158.12,37.47 158.12,36.83 158.75,36.2 C11.2 158.75,34.93 157.48,33.66 157.48,13.97 U$2.BN2 | E9.8 173.35,37.47 173.35,36.83 173.99,36.2 C9.2 173.99,34.93 170.81,31.75 170.81,26.67 C23.- | v175.9,15.24 175.9,13.97 U$2.BF1 | C1.2 252.73,36.2 252.09,36.83 252.09,37.47 E1.8 | E3.8 237.49,36.83 C3.2 237.49,34.93 238.12,34.29 238.12,26.67 C22.- | v254.63,15.24 254.63,13.97 U$2.AC1 | v226.06,15.24 226.06,13.97 U$2.AN2 | v213.36,15.24 213.36,13.97 U$2.AT2 | C8.2 191.77,36.2 191.13,36.83 191.13,37.47 E8.7 189.87,37.47 189.87,17.78 186.06,13.97 U$2.BC1 | C4.2 222.25,36.83 E4.8 219.07,40.01 219.07,45.72 E6.12 | v213.36,15.24 207.01,21.59 C6.2 | v213.36,15.24 v217.17,15.24 | E9.1 173.99,57.15 C10.2 173.99,67.31 E10.7 | E14.7 143.51,67.31 C14.2 | E11.1 158.75,57.15 C12.2 158.75,67.31 E12.7 | C7.2 207.01,66.68 206.38,67.31 206.38,67.95 E7.7 205.1,69.22 205.1,70.49 E7.6 207.65,71.12 | E7.9 207.65,71.12 | 207.65,71.12 207.65,76.84 E7.3 | E2.7 252.73,67.31 C2.2 252.09,66.04 252.09,56.52 E1.1 247.01,51.44 247.01,14.61 246.38,13.97 U$2.AF1 | E4.1 222.25,57.15 C5.2 | E5.8 222.25,67.31 C5.2 | E5.5 222.88,74.3 222.88,66.04 C5.2 | v9.53,15.24 9.53,13.97 U$2.DT2 | E20.8 23.5,37.47 23.5,36.83 24.13,36.2 C20.2 24.13,13.97 U$2.DN2 | E20.1 24.13,57.15 C21.2 24.13,67.31 E21.7 | U$2.DF1 41.91,13.97 C19.2 41.91,36.2 41.27,36.83 41.27,37.47 E19.8 43.81,41.28 43.81,55.88 E19.1 | 143.51,20.32 v143.51,15.24 143.51,13.97 U$2.BT2 | 143.51,20.32 143.51,28.58 | 143.51,28.58 C13.2 | 143.51,28.58 151.76,36.83 151.76,43.82 E13.12 | E15.14 109.22,35.56 109.22,28.58 107.31,26.67 C24.- | C24.- 107.31,24.13 111.12,20.32 111.12,13.97 U$2.CF1 113.03,13.97 113.03,15.24 119.38,15.24 120.65,13.97 U$2.CC1 122.56,13.97 122.56,20.32 143.51,20.32
  Top 0.762: E18.8 57.15,67.31 C18.2 57.15,57.15 61.59,52.71 61.59,43.82 | 61.59,43.82 61.59,40.64 57.15,36.2 C17.2 57.15,34.93 55.88,33.66 55.88,17.15 52.7,13.97 U$2.DC1 | 61.59,43.82 E17.12 64.77,45.72 81.28,29.21 | 96.52,78.74 87,88.27 87,90.81 GND.1 | 96.52,78.74 IC1.4 | 81.28,34.29 80.64,34.93 80.64,36.2 E16.14 | 81.28,34.29 83.19,34.29 83.19,35.56 C16.2 83.82,66.04 96.52,78.74 | 81.28,24.77 81.28,13.97 U$2.CT2 | 81.28,24.77 81.28,29.21 | 81.28,29.21 81.28,34.29 | 81.28,24.77 92.08,13.97 U$2.CN2 93.98,13.97 93.98,24.77 105.41,24.77 C24.-
  Bottom 0.762: 170.81,15.24 170.81,24.13 C23.- | 170.81,15.24 173.35,15.24 174.62,13.97 U$2.BF2 175.9,13.97 v175.9,15.24 182.88,15.24 184.15,13.97 U$2.BC2 | 170.81,15.24 158.75,15.24 157.48,13.97 U$2.BN2 155.57,13.97 154.31,15.24 146.05,15.24 144.78,13.97 U$2.BT2 143.51,13.97 v143.51,15.24 | E11.8 158.75,38.1 162.56,41.91 169.54,41.91 170.81,40.64 170.81,38.74 172.09,38.74 E9.8 | C1.2 252.09,35.56 242.57,26.04 240.03,26.04 C22.- 240.03,24.77 248.28,16.51 248.92,16.51 | 248.92,16.51 249.56,17.15 253.37,17.15 254,16.51 254,15.24 | 248.92,16.51 246.38,13.97 U$2.AF2 | 254,15.24 254,13.97 U$2.AC2 | 254,15.24 v254.63,15.24 | v226.06,15.24 226.06,13.97 U$2.AN2 225.43,13.97 224.16,15.24 v217.17,15.24 | v213.36,15.24 213.36,13.97 U$2.AT2 | 208.91,34.29 207.65,35.56 C6.2 | 208.91,34.29 220.34,34.29 221.62,35.56 C4.2 | 208.91,34.29 193.68,34.29 192.41,35.56 C8.2 | E4.8 225.43,38.1 226.69,36.83 233.68,36.83 234.95,38.1 E3.8 241.94,43.82 241.94,46.99 245.11,46.99 245.75,47.63 245.75,57.15 | C9.2 176.53,35.56 177.8,36.83 187.96,36.83 189.23,38.1 E8.7 | 154.94,67.31 145.41,67.31 144.15,66.04 C14.2 | 154.94,67.31 156.21,68.58 E12.7 | 154.94,67.31 170.18,67.31 171.45,68.58 E10.7 | 233.68,57.15 234.95,55.88 E3.1 | 233.68,57.15 223.52,57.15 222.25,55.88 E4.1 | 245.75,57.15 233.68,57.15 | 245.75,57.15 248.92,57.15 250.19,55.88 E1.1 | E7.9 214.63,71.12 217.17,68.58 E5.8 | C10.2 174.62,66.04 175.9,67.31 203.2,67.31 204.47,68.58 E7.7 | v9.53,15.24 9.53,13.97 U$2.DT2 11.43,13.97 12.7,15.24 20.95,15.24 22.23,13.97 U$2.DN2 24.13,13.97 32.38,22.23 34.29,22.23 C25.- | C25.- 34.92,24.13 24.13,34.93 C20.2 24.77,35.56 26.04,36.83 36.83,36.83 38.1,35.56 C19.2
  Bottom 0.762: 41.27,15.24 41.27,21.59 36.2,21.59 C25.- | 41.27,15.24 41.27,13.97 U$2.DF2 | 41.27,15.24 49.53,15.24 50.8,13.97 U$2.DC2 | E19.1 39.37,55.88 38.1,57.15 25.4,57.15 24.13,55.88 E20.1 | U$2.CT2 81.28,13.97 82.55,15.24 90.81,15.24 92.08,13.97 U$2.CN2 93.98,13.97 104.78,24.77 105.41,24.77 C24.- 107.31,24.13 111.12,24.13 111.12,15.24 | C15.2 116.84,36.2 114.94,38.1 E15.14 | 111.12,15.24 111.12,13.97 U$2.CF2 | 111.12,15.24 119.38,15.24 120.65,13.97 U$2.CC2 | E18.9 E18.8 54.61,68.58 53.34,69.85 25.4,69.85 24.13,68.58 E21.7
LMEM00
  Bottom 0.254: E6.9 214.63,38.1 215.9,39.37 229.87,39.37 230.5,40.01 230.5,47.63 229.24,47.63 E4.13
LMEM01  (via drill 0.61)
  Top 0.254: v217.81,44.45 217.81,43.82 214.63,40.64 E6.10
  Bottom 0.254: v217.81,44.45 226.06,44.45 227.33,43.18 E4.11
LMEM02
  Top 0.254: E4.5 E6.15
LMEM03
  Top 0.254: E4.4 E6.16
LMEM04
  Bottom 0.254: E13.9 151.13,38.1 154.94,41.91 161.29,41.91 162.56,43.18 E11.11
LMEM05  (via drill 0.61)
  Top 0.254: v161.93,44.45 163.19,45.72 163.19,46.36 E11.13
  Bottom 0.254: v161.93,44.45 154.94,44.45 151.13,40.64 E13.10
LMEM06
  Top 0.254: E11.5 156.21,45.72 151.76,50.17 151.76,51.44 E13.15
LMEM07
  Top 0.254: E11.4 154.94,48.26 154.94,50.8 E13.16
LMEM08
  Bottom 0.254: E20.11 31.75,43.18 38.1,36.83 60.96,36.83 62.23,38.1 E17.9
LMEM09
  Bottom 0.254: E20.13 28.57,46.36 28.57,44.45 41.91,44.45 46.99,39.37 60.96,39.37 62.23,40.64 E17.10
LMEM10  (via drill 0.61)
  Top 0.254: v58.42,58.42 E17.15
  Bottom 0.254: v58.42,58.42 18.41,58.42 18.41,50.17 E20.5
LMEM11
  Top 0.254: E20.4 27.3,52.71 27.3,83.19 29.21,85.09 53.98,85.09 53.98,70.49 54.61,69.85 60.33,69.85 60.33,59.06 E17.16
MA00  (via drill 0.61)
  Top 0.254: v142.24,28.58 128.91,41.91 128.91,56.52 E15.23
  Bottom 0.254: E16.23 95.25,58.42 96.52,57.15 124.46,57.15 125.73,58.42 E15.23 | v142.24,28.58 237.49,28.58 245.75,36.83 254,36.83 257.81,40.64 E1.10
MA00L
  Top 0.254: E1.9 259.08,20.96 252.73,14.61 252.73,13.97 U$2.AD1
MA01  (via drill 0.61)
  Top 0.254: v253.37,62.23 253.37,52.71 E1.3 | v125.09,62.23 125.09,55.25 E15.21
  Bottom 0.254: E16.21 95.25,53.34 95.89,52.71 109.86,52.71 110.49,52.07 124.46,52.07 125.73,53.34 E15.21 | v253.37,62.23 252.73,61.6 128.91,61.6 128.27,62.23 v125.09,62.23
MA01L
  Top 0.254: E1.2 248.28,50.17 248.28,13.97 U$2.AE1
MA02
  Bottom 0.254: E16.24 95.25,60.96 95.89,60.33 109.86,60.33 110.49,59.69 123.19,59.69 124.46,60.96 E15.24 260.99,60.96 260.99,47.63 260.35,46.99 257.81,46.99 255.27,44.45 248.92,44.45 245.11,40.64 E3.10
MA02L
  Top 0.254: E3.9 243.84,14.61 243.21,13.97 U$2.AH1
MA03  (via drill 0.61)
  Top 0.254: v231.78,62.87 238.12,56.52 238.12,45.09 E3.6
  Bottom 0.254: E16.25 95.25,63.5 96.52,62.23 123.83,62.23 125.09,63.5 E15.25 231.14,63.5 v231.78,62.87
MA03L
  Top 0.254: E3.7 240.66,36.2 240.66,14.61 240.03,13.97 U$2.AJ1
MA04  (via drill 0.61)
  Top 0.254: v121.92,54.61 113.67,62.87 113.67,64.14 E15.3
  Bottom 0.254: E16.3 80.01,66.04 81.28,67.31 95.25,67.31 96.52,66.04 E15.3 | v121.92,54.61 175.26,54.61 179.07,50.8 E9.14
MA04L
  Top 0.254: E9.15 177.8,55.88 177.8,66.68 178.44,67.31 183.51,67.31 183.51,14.61 182.88,13.97 U$2.BD1
MA05  (via drill 0.61)
  Top 0.254: v125.09,36.83 113.67,48.26 113.67,61.6 E15.4
  Bottom 0.254: E16.4 80.01,63.5 81.28,64.77 109.22,64.77 110.49,63.5 E15.4 | v125.09,36.83 175.26,36.83 179.07,40.64 E9.10
MA05L
  Top 0.254: E9.9 180.34,14.61 179.71,13.97 U$2.BE1
MA06  (via drill 0.61)
  Top 0.254: v166.37,29.85 166.37,36.83 E9.6 | v107.95,29.85 107.95,57.15 E15.5
  Bottom 0.254: E16.5 80.01,60.96 81.28,62.23 95.25,62.23 96.52,60.96 E15.5 | v107.95,29.85 v166.37,29.85
MA06L
  Top 0.254: E9.7 175.26,38.1 175.26,15.88 173.35,13.97 U$2.BH1
MA07  (via drill 0.61)
  Top 0.254: v175.26,58.42 175.26,53.34 E9.3
  Bottom 0.254: E16.6 80.01,58.42 81.28,59.69 109.22,59.69 110.49,58.42 E15.6 123.19,58.42 124.46,59.69 173.99,59.69 v175.26,58.42
MA07L  (via drill 0.61)
  Top 0.254: v168.91,40.64 168.91,49.53 E9.2 | v168.91,38.1 168.28,37.47 168.28,13.97 U$2.BJ1
  Bottom 0.254: v168.91,38.1 v168.91,40.64
MA08  (via drill 0.61)
  Top 0.254: v46.35,57.15 46.35,52.71 E19.14
  Bottom 0.254: v46.35,57.15 76.2,57.15 | 76.2,57.15 77.47,55.88 E16.7 | 76.2,57.15 95.25,57.15 95.89,56.52 109.86,56.52 110.49,55.88 E15.7
MA08L
  Top 0.254: E19.15 50.16,51.44 50.16,14.61 49.53,13.97 U$2.DD1
MA09  (via drill 0.61)
  Top 0.254: v73.66,46.36 76.83,49.53 76.83,51.44 E16.8
  Bottom 0.254: v73.66,46.36 73.03,46.36 71.12,44.45 53.34,44.45 49.53,40.64 E19.10 | E15.8 110.49,53.34 109.86,53.98 95.89,53.98 95.25,54.61 81.28,54.61 80.01,53.34 E16.8
MA09L
  Top 0.254: E19.9 48.26,15.88 46.35,13.97 U$2.DE1
MA10  (via drill 0.61)
  Top 0.254: v42.55,54.61 42.55,45.09 E19.6
  Bottom 0.254: v42.55,54.61 73.66,54.61 76.2,52.07 | 76.2,52.07 77.47,50.8 E16.9 | 76.2,52.07 109.22,52.07 110.49,50.8 E15.9
MA10L
  Top 0.254: E19.7 38.73,38.74 38.73,13.97 U$2.DH1
MA11  (via drill 0.61)
  Top 0.254: v69.22,49.53 73.66,45.09 76.83,45.09 76.83,46.36 E16.10 80.64,46.36 80.64,43.82 v82.55,41.91 | v109.22,41.91 109.22,45.72 E15.10
  Bottom 0.254: v69.22,49.53 43.18,49.53 41.91,50.8 E19.3 | v82.55,41.91 v109.22,41.91
MA11L
  Top 0.254: E19.2 37.47,50.17 37.47,14.61 36.83,13.97 U$2.DJ1
MD00L  (via drill 0.61)
  Top 0.254: v231.78,53.34 233.04,52.07 233.04,19.05 232.41,18.42 232.41,16.51 234.95,13.97 U$2.AK1
  Bottom 0.254: E4.15 v231.78,53.34
MD01L  (via drill 0.61)
  Top 0.254: v231.78,38.1 231.78,13.97 U$2.AL1
  Bottom 0.254: E4.9 v231.78,38.1
MD02L  (via drill 0.61)
  Top 0.254: v223.52,17.15 223.52,38.1 E4.7 | v226.06,16.51 228.6,13.97 U$2.AM1
  Bottom 0.254: v223.52,17.15 224.16,16.51 v226.06,16.51
MD03L
  Top 0.254: E4.2 224.16,50.17 224.16,17.78 224.79,17.15 224.79,14.61 224.16,13.97 U$2.AP1
MD04L
  Top 0.254: E11.9 165.1,13.97 U$2.BK1
MD05L
  Top 0.254: E11.15 167,51.44 167,40.01 166.37,39.37 162.56,39.37 162.56,13.97 U$2.BL1
MD06L
  Top 0.254: E11.7 160.02,38.1 160.02,13.97 U$2.BM1
MD07L
  Top 0.254: E11.2 159.38,51.44 159.38,42.55 158.75,41.91 154.31,41.91 154.31,13.97 U$2.BP1
MD08L
  Top 0.254: E20.9 31.75,36.83 31.75,13.97 U$2.DK1
MD09L
  Top 0.254: E20.15 28.57,51.44 28.57,45.09 29.21,44.45 32.38,44.45 32.38,40.01 31.75,39.37 27.94,39.37 27.94,14.61 28.57,13.97 U$2.DL1
MD10L
  Top 0.254: E20.7 25.4,38.1 25.4,13.97 U$2.DM1
MD11L  (via drill 0.61)
  Top 0.254: v19.68,50.17 19.68,13.97 U$2.DP1
  Bottom 0.254: v19.68,50.17 E20.2
MD_DIRL  (via drill 0.61)
  Top 0.254: v229.87,17.15 224.79,22.23 224.79,54.61 219.71,54.61 219.07,55.25 219.07,57.15 214,57.15 203.84,67.31 203.84,71.76 E7.5
  Bottom 0.254: v229.87,17.15 232.41,14.61 234.31,14.61 234.95,13.97 U$2.AK2
MEM00  (via drill 0.61)
  Top 0.254: v99.69,33.66 95.25,38.1 E16.15 | E8.11 200.03,43.82 200.03,33.02 201.29,31.75 203.84,31.75 203.84,38.74 E6.7
  Bottom 0.254: v99.69,33.66 100.33,33.02 187.32,33.02 191.13,36.83 200.66,36.83 204.47,40.64 E6.7
MEM01  (via drill 0.61)
  Top 0.254: v81.92,35.56 81.92,37.47 E16.13 | v196.22,32.39 198.12,34.29 E8.8
  Bottom 0.254: v81.92,35.56 85.09,32.39 v196.22,32.39 | E6.6 204.47,43.18 203.2,41.91 196.85,41.91 196.22,41.28 196.22,38.74 197.49,38.74 E8.8
MEM02  (via drill 0.61)
  Top 0.254: v85.09,40.64 87.63,38.1 v87.63,27.31 | 187.96,30.48 188.59,31.12 188.59,38.74 E8.6 | 187.96,30.48 v184.78,27.31 | v201.29,33.02 201.29,46.36 E6.3 | v188.59,29.85 187.96,30.48
  Bottom 0.254: v85.09,40.64 82.55,40.64 80.01,43.18 E16.12 | v184.78,27.31 v87.63,27.31 | v201.29,33.02 198.12,29.85 v188.59,29.85
MEM03  (via drill 0.61)
  Top 0.254: v76.83,35.56 76.83,43.82 E16.11 | v191.13,31.12 193.04,33.02 193.04,45.72 192.41,46.36 | 192.41,46.36 E8.3 | 192.41,46.36 192.41,57.79 200.03,57.79 204.47,53.34 E6.2
  Bottom 0.254: v76.83,35.56 80.64,31.75 190.5,31.75 v191.13,31.12
MEM04  (via drill 0.61)
  Top 0.254: E13.7 140.34,40.64 v132.72,48.26 v132.72,69.22
  Bottom 0.254: E15.19 v132.72,48.26 | v132.72,69.22 140.97,77.47 147.32,77.47 148.59,76.2 E14.11
MEM05  (via drill 0.61)
  Top 0.254: v146.05,45.72 146.05,66.04 148.59,68.58 E14.8
  Bottom 0.254: E15.18 128.27,45.72 130.81,43.18 E13.6 143.51,43.18 v146.05,45.72
MEM06  (via drill 0.61)
  Top 0.254: v140.34,41.91 140.34,48.9 | 140.34,48.9 E13.3 | 140.34,48.9 140.34,69.22 E14.6
  Bottom 0.254: v140.34,41.91 129.54,41.91 128.27,43.18 E15.17
MEM07  (via drill 0.61)
  Top 0.254: v124.46,50.8 124.46,43.18 E15.16 | E14.3 144.78,76.2 144.78,55.88 E13.2
  Bottom 0.254: v124.46,50.8 125.73,52.07 137.79,52.07 139.06,53.34 E13.2
MEM08  (via drill 0.61)
  Top 0.254: 53.98,42.55 50.8,45.72 v50.8,60.96 | v43.18,64.77 31.75,76.2 E21.11 | 53.98,42.55 E17.7 | v55.24,35.56 53.98,36.83 53.98,42.55 | v127,28.58 E15.15
  Bottom 0.254: v50.8,60.96 46.99,64.77 v43.18,64.77 | v127,28.58 62.23,28.58 v55.24,35.56
MEM09  (via drill 0.61)
  Top 0.254: v46.99,67.31 53.34,60.96 53.34,45.72 E17.6
  Bottom 0.254: v46.99,67.31 33.02,67.31 31.75,68.58 E21.8 | E15.13 110.49,40.64 109.22,39.37 67.31,39.37 64.77,41.91 58.42,41.91 57.15,43.18 E17.6
MEM10  (via drill 0.61)
  Top 0.254: v19.68,56.52 19.68,74.93 24.13,74.93 24.77,74.3 24.77,73.03 E21.6 | v105.41,73.03 v105.41,43.18
  Bottom 0.254: v19.68,56.52 21.59,54.61 36.83,54.61 39.37,52.07 53.34,52.07 54.61,50.8 E17.3 | v105.41,73.03 65.41,73.03 64.77,72.39 25.4,72.39 24.13,71.12 E21.6 | v105.41,43.18 E15.12
MEM11  (via drill 0.61)
  Top 0.254: v54.61,59.69 53.98,59.06 53.98,55.25 E17.2 | v66.04,50.8 v72.39,44.45
  Bottom 0.254: v54.61,59.69 20.95,59.69 20.95,76.84 E21.3 | v72.39,44.45 109.22,44.45 110.49,45.72 E15.11 | v66.04,50.8 64.77,52.07 58.42,52.07 57.15,53.34 E17.2
MINE
  Bottom 0.254: E2.8 257.81,68.58 254,72.39 182.88,72.39 181.61,71.12 E10.9 176.53,71.12 173.99,73.66 E10.5
N$1
  Bottom 0.254: E5.7 222.25,71.12 223.52,69.85 239.4,69.85 240.03,69.22 240.03,66.68 238.76,66.68 SV2.2
N$18
  Bottom 0.254: E5.9 SV2.4
N$19
  Bottom 0.254: E5.10 SV2.6
N$20
  Bottom 0.254: E5.11 SV2.8
N$21
  Bottom 0.254: E5.12 SV2.10
N$22
  Bottom 0.254: E5.13 SV2.12
N$23
  Bottom 0.254: E5.14 SV2.14
N$24
  Bottom 0.254: E5.15 SV2.16
N$25
  Top 0.254: C99.1 R3.2
  Bottom 0.254: R3.2 E18.7
N$26
  Top 0.254: SV2.9 E2.4
N$27
  Top 0.254: SV2.11 E2.3
N$28
  Top 0.254: SV2.13 E2.2
N$29
  Top 0.254: SV2.15 E2.1
N$30
  Top 0.254: SV2.7 E2.5
N$31
  Top 0.254: E2.11 252.73,69.85 243.21,69.85 243.21,68.58 241.3,66.68 SV2.1
N$32
  Top 0.254: E2.12 252.73,72.39 242.57,72.39 242.57,70.49 241.3,69.22 SV2.3
N$33
  Bottom 0.254: SV2.5 E2.6
N$34
  Bottom 0.254: C99.2 48.9,76.2 51.44,73.66 E18.6
N$35
  Top 0.254: E16.18 92.08,43.82 92.08,42.55 92.71,41.91 100.97,41.91 100.97,48.26 R4.1
N$36
  Bottom 0.254: E12.4 158.75,76.2 160.02,77.47 170.18,77.47 171.45,76.2 E10.4
N$37
  Top 0.254: E12.6 156.84,71.76 156.84,73.03 E12.5
  Bottom 0.254: 185.42,76.2 184.15,76.2 181.61,73.66 E10.10 | 185.42,76.2 E7.4 | 185.42,76.2 181.61,80.01 163.83,80.01 163.19,79.38 160.66,79.38 158.75,77.47 155.57,77.47 155.57,75.57 E12.5
N$38
  Top 0.254: E16.16 106.68,40.64 R2.1
N$39
  Bottom 0.254: E10.1 173.99,83.82 175.26,85.09 203.2,85.09 204.47,83.82 E7.1
N$40
  Bottom 0.254: E7.10 E7.2
N$41
  Top 0.254: E10.3 171.45,78.74 167,83.19 167,84.46 166.37,85.09 145.41,85.09 145.41,51.44 E13.4
  Bottom 0.254: E6.13 E6.4 204.47,48.26 203.2,49.53 152.4,49.53 151.13,48.26 E13.13 E13.4 140.97,48.26 139.7,49.53 77.47,49.53 76.2,48.26 E17.13 E17.4
N$42
  Top 0.254: E18.5 61.59,81.92 61.59,87 75.56,100.97 178.44,100.97 178.44,83.19 E10.13
N$43
  Top 0.254: E12.11 164.47,76.84 164.47,78.11 E12.12
  Bottom 0.254: E10.11 179.07,76.2 177.8,74.93 167.64,74.93 166.37,76.2 E12.11
N$44
  Top 0.254: E16.17 100.33,43.18 100.33,48.9 100.97,49.53 104.14,49.53 R1.1
N$45
  Bottom 0.254: E16.19 R5.1
READM  (via drill 0.61)
  Top 0.254: E10.2 175.26,81.28 175.26,73.66 E10.8 177.16,68.58 v177.16,46.99
  Bottom 0.254: 162.56,46.99 77.47,46.99 76.83,47.63 73.66,47.63 73.03,46.99 33.02,46.99 31.75,45.72 E20.12 | 162.56,46.99 163.83,45.72 E11.12 | 162.56,46.99 v177.16,46.99 226.06,46.99 227.33,45.72 E4.12
ROM_ADDR  (via drill 0.61)
  Top 0.254: v226.69,52.07 225.43,53.34 225.43,74.3 E5.4
  Bottom 0.254: v226.69,52.07 233.68,52.07 234.95,50.8 E3.3
ROM_ADDR_L  (via drill 0.61)
  Top 0.254: v233.68,18.42 233.68,50.8 E3.2
  Bottom 0.254: v233.68,18.42 215.26,18.42 210.82,13.97 U$2.AU2
STROBEH  (via drill 0.61)
  Top 0.254: v230.5,67.31 230.5,17.78 231.14,17.15 231.14,15.88 v230.5,15.24
  Bottom 0.254: v230.5,67.31 215.9,67.31 214.63,68.58 E7.8 | v230.5,15.24 230.5,13.97 U$2.AM2
VCC
  Top 0.762: 219.07,71.76 219.07,66.04 C7.1 | 219.07,71.76 E5.6 | 219.07,71.76 219.07,78.11 E7.14 | E4.16 227.33,57.15 C5.1 | E3.5 235.59,46.36 235.59,47.63 E3.4 | 257.81,64.77 257.81,57.15 E1.16 E1.4 250.82,47.63 250.82,46.36 E1.5 | 257.81,64.77 C2.1 | 257.81,64.77 260.99,67.95 260.99,81.92 E2.14 | C23.+ 193.68,26.67 193.68,31.75 196.85,34.93 C8.1 196.85,36.2 194.94,38.1 194.94,50.17 E8.14 | C6.1 211.46,35.56 207.65,39.37 207.65,43.82 E6.5 | E1.13 258.44,47.63 258.44,46.36 E1.12 258.44,45.09 258.44,43.82 E1.11 257.18,41.28 257.18,36.83 257.81,36.2 C1.1 | E3.13 243.21,47.63 243.21,46.36 E3.12 243.21,45.09 243.21,43.82 E3.11 241.94,41.28 241.94,36.83 242.57,36.2 C3.1 | E20.16 29.21,57.15 C21.1 | C18.1 62.23,66.68 61.59,67.31 61.59,71.76 E18.11 65.41,75.57 65.41,84.46 E18.16 | E21.14 50.8,83.82 R3.1 50.8,80.65 45.72,75.57 45.72,58.42 | E19.5 40.01,46.36 40.01,47.63 E19.4 | E19.11 47.62,43.82 47.62,45.09 E19.12 47.62,46.36 47.62,47.63 E19.13 46.35,50.17 | 45.72,58.42 45.09,58.42 45.09,51.44 46.35,50.17 | 45.72,58.42 46.99,58.42 47.62,57.79 47.62,56.52 E19.16 | 46.35,50.17 46.35,36.83 46.99,36.2 C19.1 | IC1.8 104.14,81.28 R1.2 R4.2 R5.2 99.06,50.8 95.25,46.99 88.9,46.99 C16.1 | C17.1 62.23,34.93 59.05,31.75 59.05,24.13 C25.+ | C15.1 121.92,34.93 125.73,31.12 125.73,27.94 128.27,25.4 C24.+ | C13.1 148.59,36.2 144.15,40.64 144.15,43.82 E13.5 | E11.16 163.83,57.15 C12.1 163.19,66.04 163.19,81.92 E12.14 | E9.4 172.09,47.63 172.09,46.36 E9.5 E9.12 | C9.1 179.07,36.2 178.44,36.83 178.44,41.28 E9.11 179.71,43.82 179.71,45.09 E9.12 | E9.12 179.71,46.36 179.71,47.63 E9.13 182.25,50.17 182.25,53.98 E9.16 179.07,57.15 C10.1
  Bottom 0.762: C1.1 257.81,26.67 260.99,26.67 C22.+ 260.99,24.13 260.99,13.97 U$2.AA2 | E5.16 227.33,86.36 223.52,82.55 215.9,82.55 214.63,83.82 E7.14 | 239.4,51.44 242.57,54.61 | 242.57,54.61 E3.16 | 239.4,51.44 E3.4 | 242.57,54.61 231.14,54.61 229.87,55.88 E4.16 | C3.1 241.94,35.56 240.66,34.29 229.24,34.29 227.97,35.56 C4.1 226.06,35.56 224.79,36.83 214,36.83 | E3.12 E1.5 | E1.4 E1.13 | 214,36.83 212.72,35.56 C6.1 | 214,36.83 206.38,36.83 205.1,35.56 C8.1 | U$2.BA2 191.77,13.97 191.77,24.77 C23.+ | 239.4,51.44 242.57,48.26 E3.13 | C7.1 212.72,66.04 214,64.77 225.43,64.77 226.69,66.04 C5.1 | R3.1 50.8,80.65 53.98,77.47 58.42,77.47 62.23,73.66 E18.11 | C21.1 55.24,66.04 56.52,67.31 60.33,67.31 61.59,66.04 C18.1 | C20.1 29.84,35.56 31.11,34.29 45.09,34.29 46.35,35.56 C19.1 46.99,34.93 57.78,24.13 C25.+ | E17.5 E19.12 E19.5 | R1.2 R2.2 | C17.1 62.87,35.56 64.14,36.83 87,36.83 88.27,35.56 C16.1 89.53,35.56 90.17,34.93 115.57,34.93 116.2,34.29 123.83,34.29 | C24.+ 128.91,24.13 128.91,17.15 128.27,16.51 128.27,13.97 U$2.CA2 | 150.5,34.29 161.93,34.29 163.19,35.56 C11.1 164.47,35.56 165.74,34.29 177.16,34.29 178.44,35.56 C9.1 | 150.5,34.29 149.22,35.56 C13.1 | E14.14 151.13,83.82 152.4,85.09 162.56,85.09 163.83,83.82 E12.14 166.37,83.82 167.64,82.55 177.8,82.55 179.07,83.82 E10.14 | C14.1 149.22,66.04 150.5,64.77 161.93,64.77 163.19,66.04 C12.1 164.47,66.04 165.74,64.77 177.16,64.77 178.44,66.04 C10.1 | E8.14 196.85,53.34 194.31,55.88 E9.16 | 123.83,34.29 122.56,35.56 C15.1 | 150.5,34.29 123.83,34.29
VCC\
  Top 0.254: 108.58,80.65 108.58,85.09 105.41,85.09 102.87,82.55 102.87,72.39 97.79,67.31 97.79,54.61 E16.20 | 108.58,80.65 IC1.6 | 108.58,80.65 108.58,67.31 113.03,67.31 114.3,66.04 114.3,63.5 E15.20
VMEM
  Top 0.254: E16.28 100.33,71.12 100.33,74.93 100.97,75.57 100.97,81.92 IC1.1
  Bottom 0.254: E15.28 125.73,71.12 114.3,82.55 101.6,82.55 100.33,83.82 IC1.1
WRITE  (via drill 0.61)
  Top 0.254: v82.55,55.88 82.55,57.15 77.47,57.15 E18.10 | v215.9,17.15 213.36,19.69 213.36,36.2 212.72,36.83 211.46,36.83 v211.46,54.61
  Bottom 0.254: v82.55,55.88 E16.22 95.25,55.88 96.52,54.61 120.65,54.61 121.92,55.88 E15.22 128.27,55.88 129.54,57.15 208.91,57.15 v211.46,54.61 | v215.9,17.15 215.9,13.97 U$2.AS2
WRITEM
  Top 0.254: E8.10 196.22,45.09 196.22,48.9 E8.13 | E8.4 188.59,47.63 188.59,51.44 E8.1 189.87,53.98 189.87,69.22 E10.12 179.07,78.74 175.26,82.55 170.81,82.55 170.81,80.65 171.45,80.01 174.62,80.01 174.62,73.03 E10.6 | E14.13 147.96,79.38 147.96,75.57 E14.10
  Bottom 0.254: E8.10 196.85,43.18 195.58,41.91 189.23,41.91 188.59,42.55 188.59,45.72 E8.4 | E21.10 26.67,73.66 24.13,76.2 E21.4 27.94,81.28 | 27.94,81.28 26.67,81.28 24.13,83.82 E21.1 | 27.94,81.28 E21.13 31.75,81.28 35.56,85.09 139.7,85.09 140.97,83.82 E14.1 143.51,83.82 146.05,81.28 E14.13 | E14.4 143.51,76.2 146.05,73.66 E14.10 151.13,73.66 152.4,72.39 170.18,72.39 171.45,71.12 E10.6
WRITEP\
  Bottom 0.254: E16.27 95.25,68.58 96.52,67.31 124.46,67.31 125.73,68.58 E15.27 128.27,68.58 139.7,80.01 162.56,80.01 163.83,81.28 E12.13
